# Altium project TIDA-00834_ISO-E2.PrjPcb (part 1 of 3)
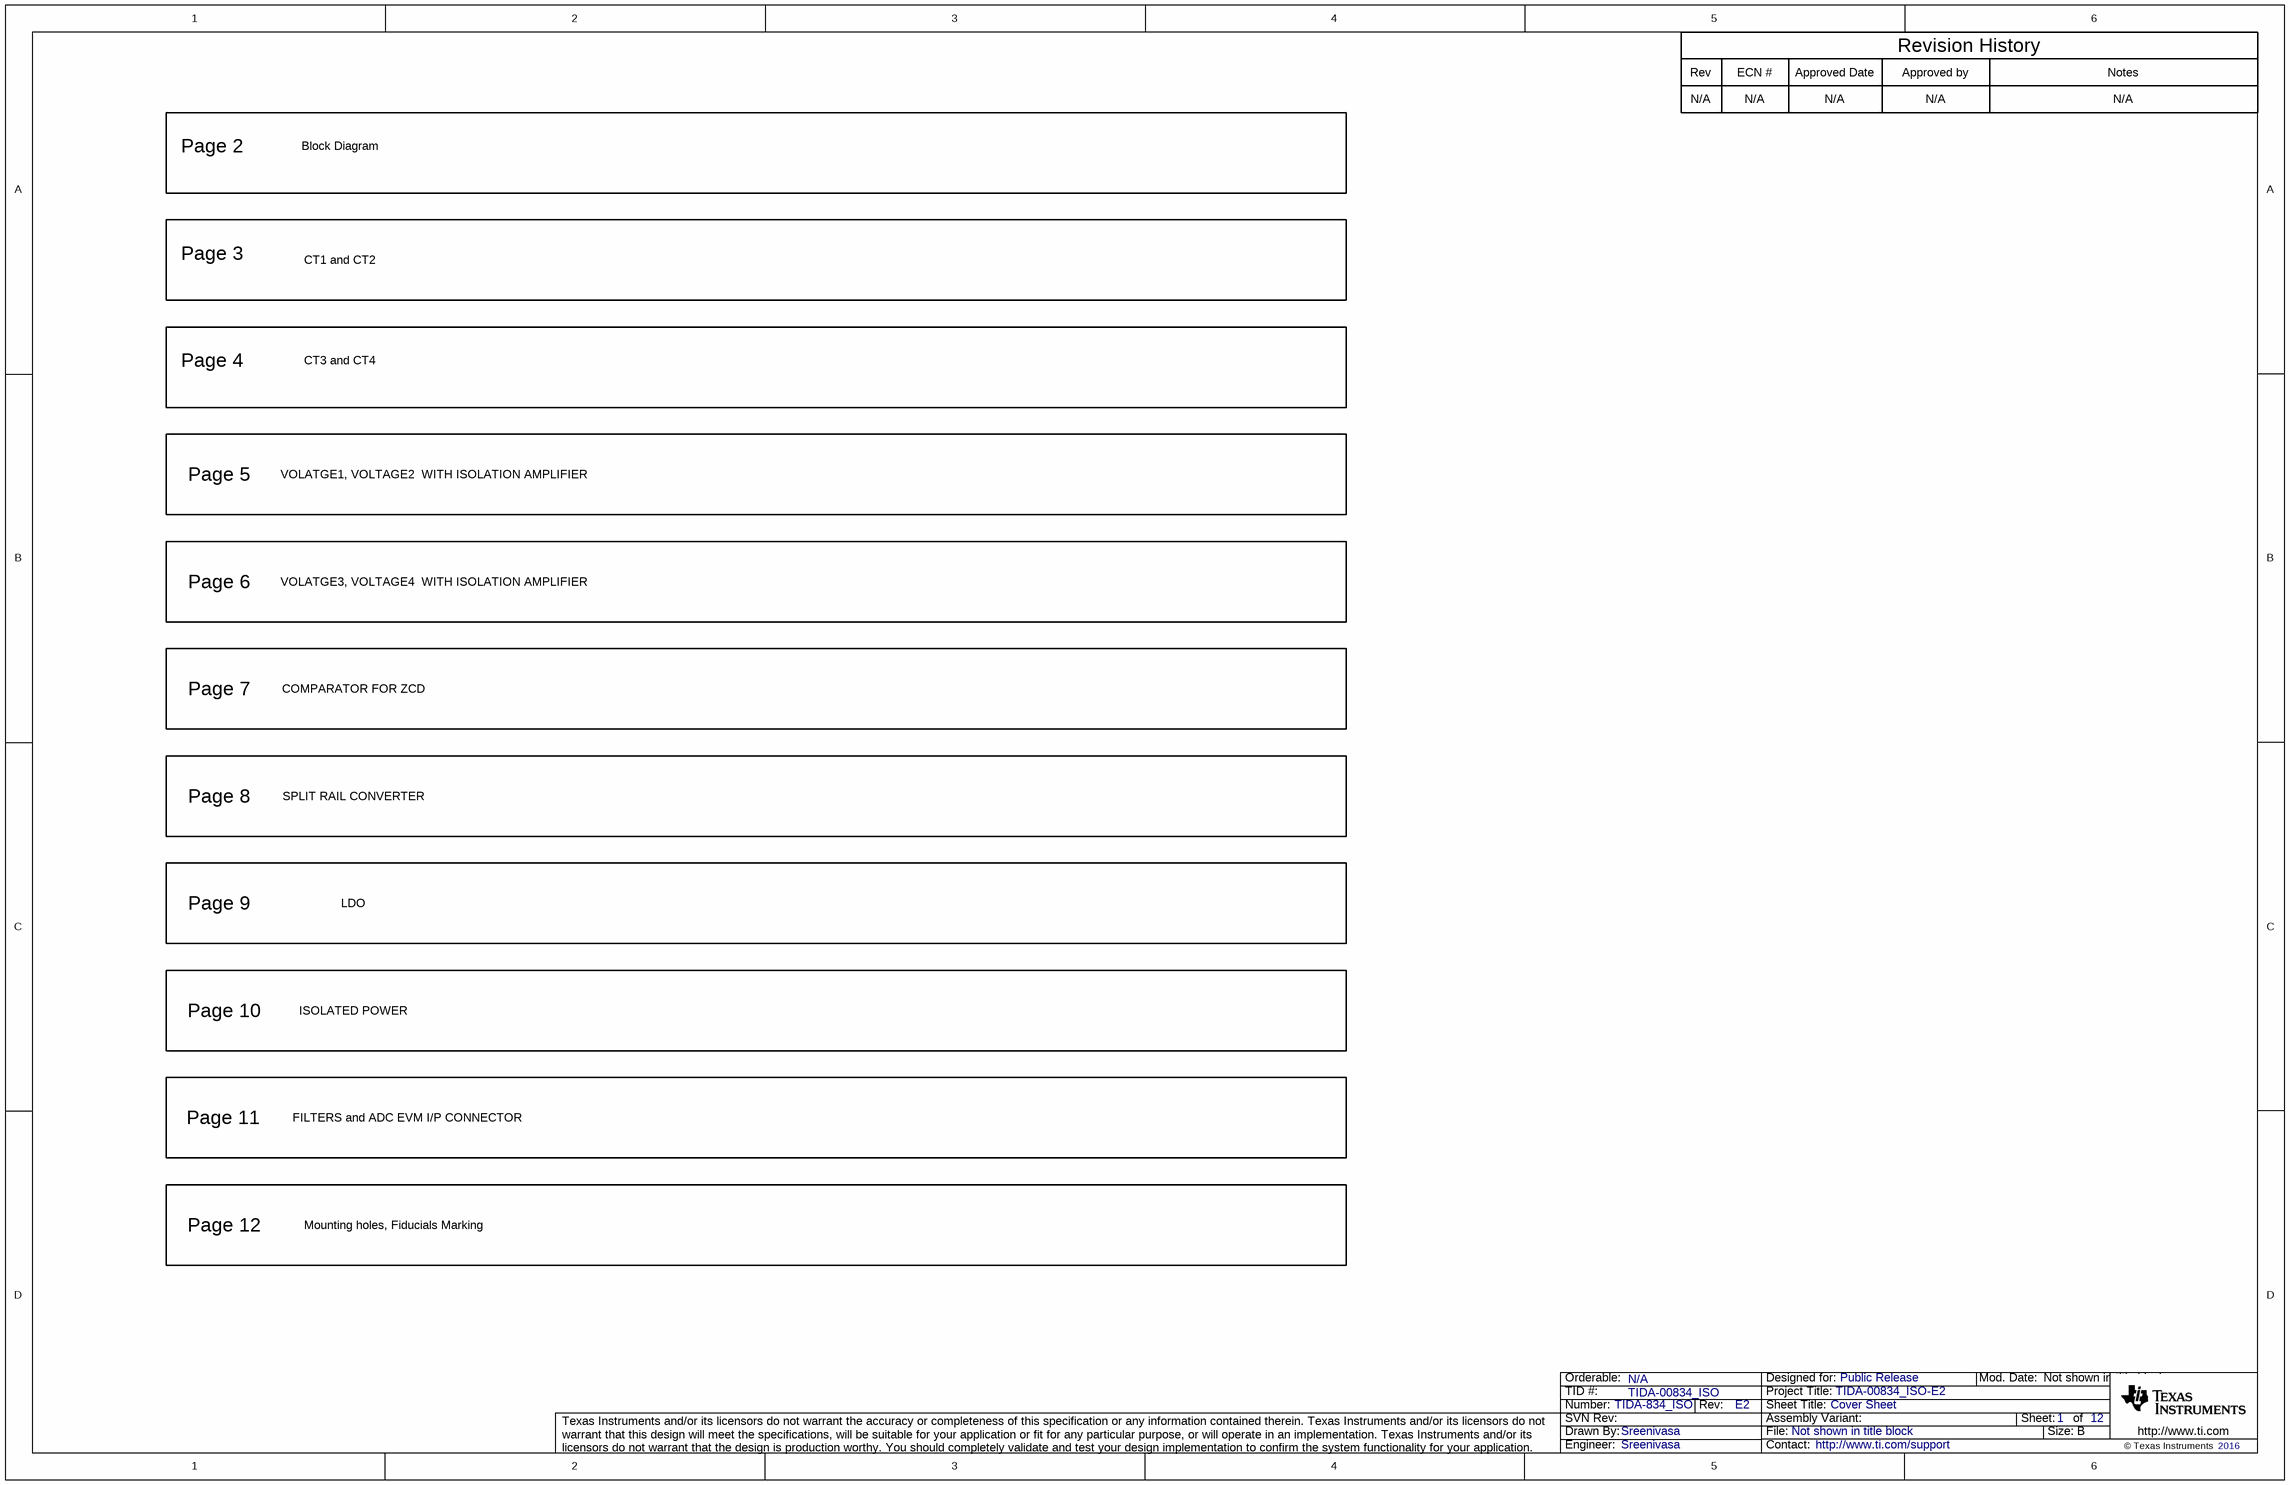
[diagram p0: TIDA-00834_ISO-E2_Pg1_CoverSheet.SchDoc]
CopyrightYear: 2016; EVM_Orderable: N/A; PCB_Layout: Manjunath M; PCB_Rev: E2; PRJ_Customer: Public Release; PRJ_Engineer: Sreenivasa; PRJ_Number: TIDA-834_ISO; PRJ_Title: TIDA-00834_ISO-E2; SCH_Rev: E2; TechSupport: http://www.ti.com/support; TID: TIDA-00834_ISO
12 sheets, 678 parts. Net scope: flat (ports and power ports of the same name join across sheets).
Board file: TIDA-00834_ISO-E2_PCB.PcbDoc
Sheets:
  TIDA-00834_ISO-E2_Pg1_CoverSheet.SchDoc
  TIDA-00834_ISO-E2_Pg2_Block Diagram.SchDoc
  TIDA-00834_ISO-E2_Pg3_CT1_CT2.SchDoc
  TIDA-00834_ISO-E2_Pg4_CT3_CT4.SchDoc
  TIDA-00834_ISO-E2_Pg5_VOLTAGE.SchDoc
  TIDA-00834_ISO-E2_Pg6_VOLTAGE2.SchDoc
  TIDA-00834_ISO-E2_Pg7_ COMPARATOR.SchDoc
  TIDA-00834_ISO-E2_Pg8_Split Rail Converter.SchDoc
  TIDA-00834_ISO-E2_Pg9_LDO.SchDoc
  TIDA-00834_ISO-E2_Pg10_ ISOPOWER.SchDoc
  TIDA-00834_ISO-E2_Pg11_Filters.SchDoc
  TIDA-00834_ISO-E2_Pg12_EVM_Hardware.SchDoc

## Sheet TIDA-00834_ISO-E2_Pg1_CoverSheet.SchDoc: Cover Sheet
size 431 x 279 mm; Date: Not shown in title block; ApprovedBy: Not shown in title block; CheckedBy: Not shown in title block; Author: Not shown in title block; CompanyName: Not shown in title block; DrawnBy: Sreenivasa; Engineer: Not shown in title block; Organization: Not shown in title block; Address1: Not shown in title block; Address2: Not shown in title block; Address3: Not shown in title block; Address4: Not shown in title block; DocumentNumber: 1; Revision: Use project parameter SCH_Rev; SheetNumber: 1; SheetTotal: 12; PageSetup: Record=PageOptions¦CenterHorizontal=True¦CenterVertical=True¦PrintScale=1.00¦XCorrection=1.00¦YCorrection=1.00¦PrintKind=0¦BorderSize=5000000¦LeftOffset=0¦BottomOffset=0¦Orientation=2¦PaperLength=1000¦PaperWidth=1000¦Scale=100¦PaperSource=15¦PrintQuality=600¦MediaType=1¦DitherType=10¦PaperKind=Letter¦PrintScaleMode=1

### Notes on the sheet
- Rev
- N/A
- ECN #
- Approved Date
- Approved by
- Revision History
- Notes
- Page 2
- Block Diagram
- Page 3
- CT1 and CT2
- Page 4
- CT3 and CT4
- Page 5
- VOLATGE1, VOLTAGE2  WITH ISOLATION AMPLIFIER
- Page 6
- VOLATGE3, VOLTAGE4  WITH ISOLATION AMPLIFIER
- Page 7
- COMPARATOR FOR ZCD
- Page 8
- SPLIT RAIL CONVERTER
- Page 9
- LDO
- Page 10
- ISOLATED POWER
- Page 11
- FILTERS and ADC EVM I/P CONNECTOR
- Page 12
- Mounting holes, Fiducials Marking

## Sheet TIDA-00834_ISO-E2_Pg2_Block Diagram.SchDoc: Block Diagram
size 431 x 279 mm; Date: Not shown in title block; ApprovedBy: Not shown in title block; CheckedBy: Not shown in title block; Author: Not shown in title block; CompanyName: Not shown in title block; DrawnBy: Sreenivasa; Engineer: Not shown in title block; Organization: Not shown in title block; Address1: Not shown in title block; Address2: Not shown in title block; Address3: Not shown in title block; Address4: Not shown in title block; DocumentNumber: 1; Revision: Use project parameter SCH_Rev; SheetNumber: 2; SheetTotal: 12; PageSetup: Record=PageOptions¦CenterHorizontal=True¦CenterVertical=True¦PrintScale=1.00¦XCorrection=1.00¦YCorrection=1.00¦PrintKind=0¦BorderSize=5000000¦LeftOffset=0¦BottomOffset=0¦Orientation=2¦PaperLength=1000¦PaperWidth=1000¦Scale=100¦PaperSource=15¦PrintQuality=600¦MediaType=1¦DitherType=10¦PaperKind=Letter¦PrintScaleMode=1
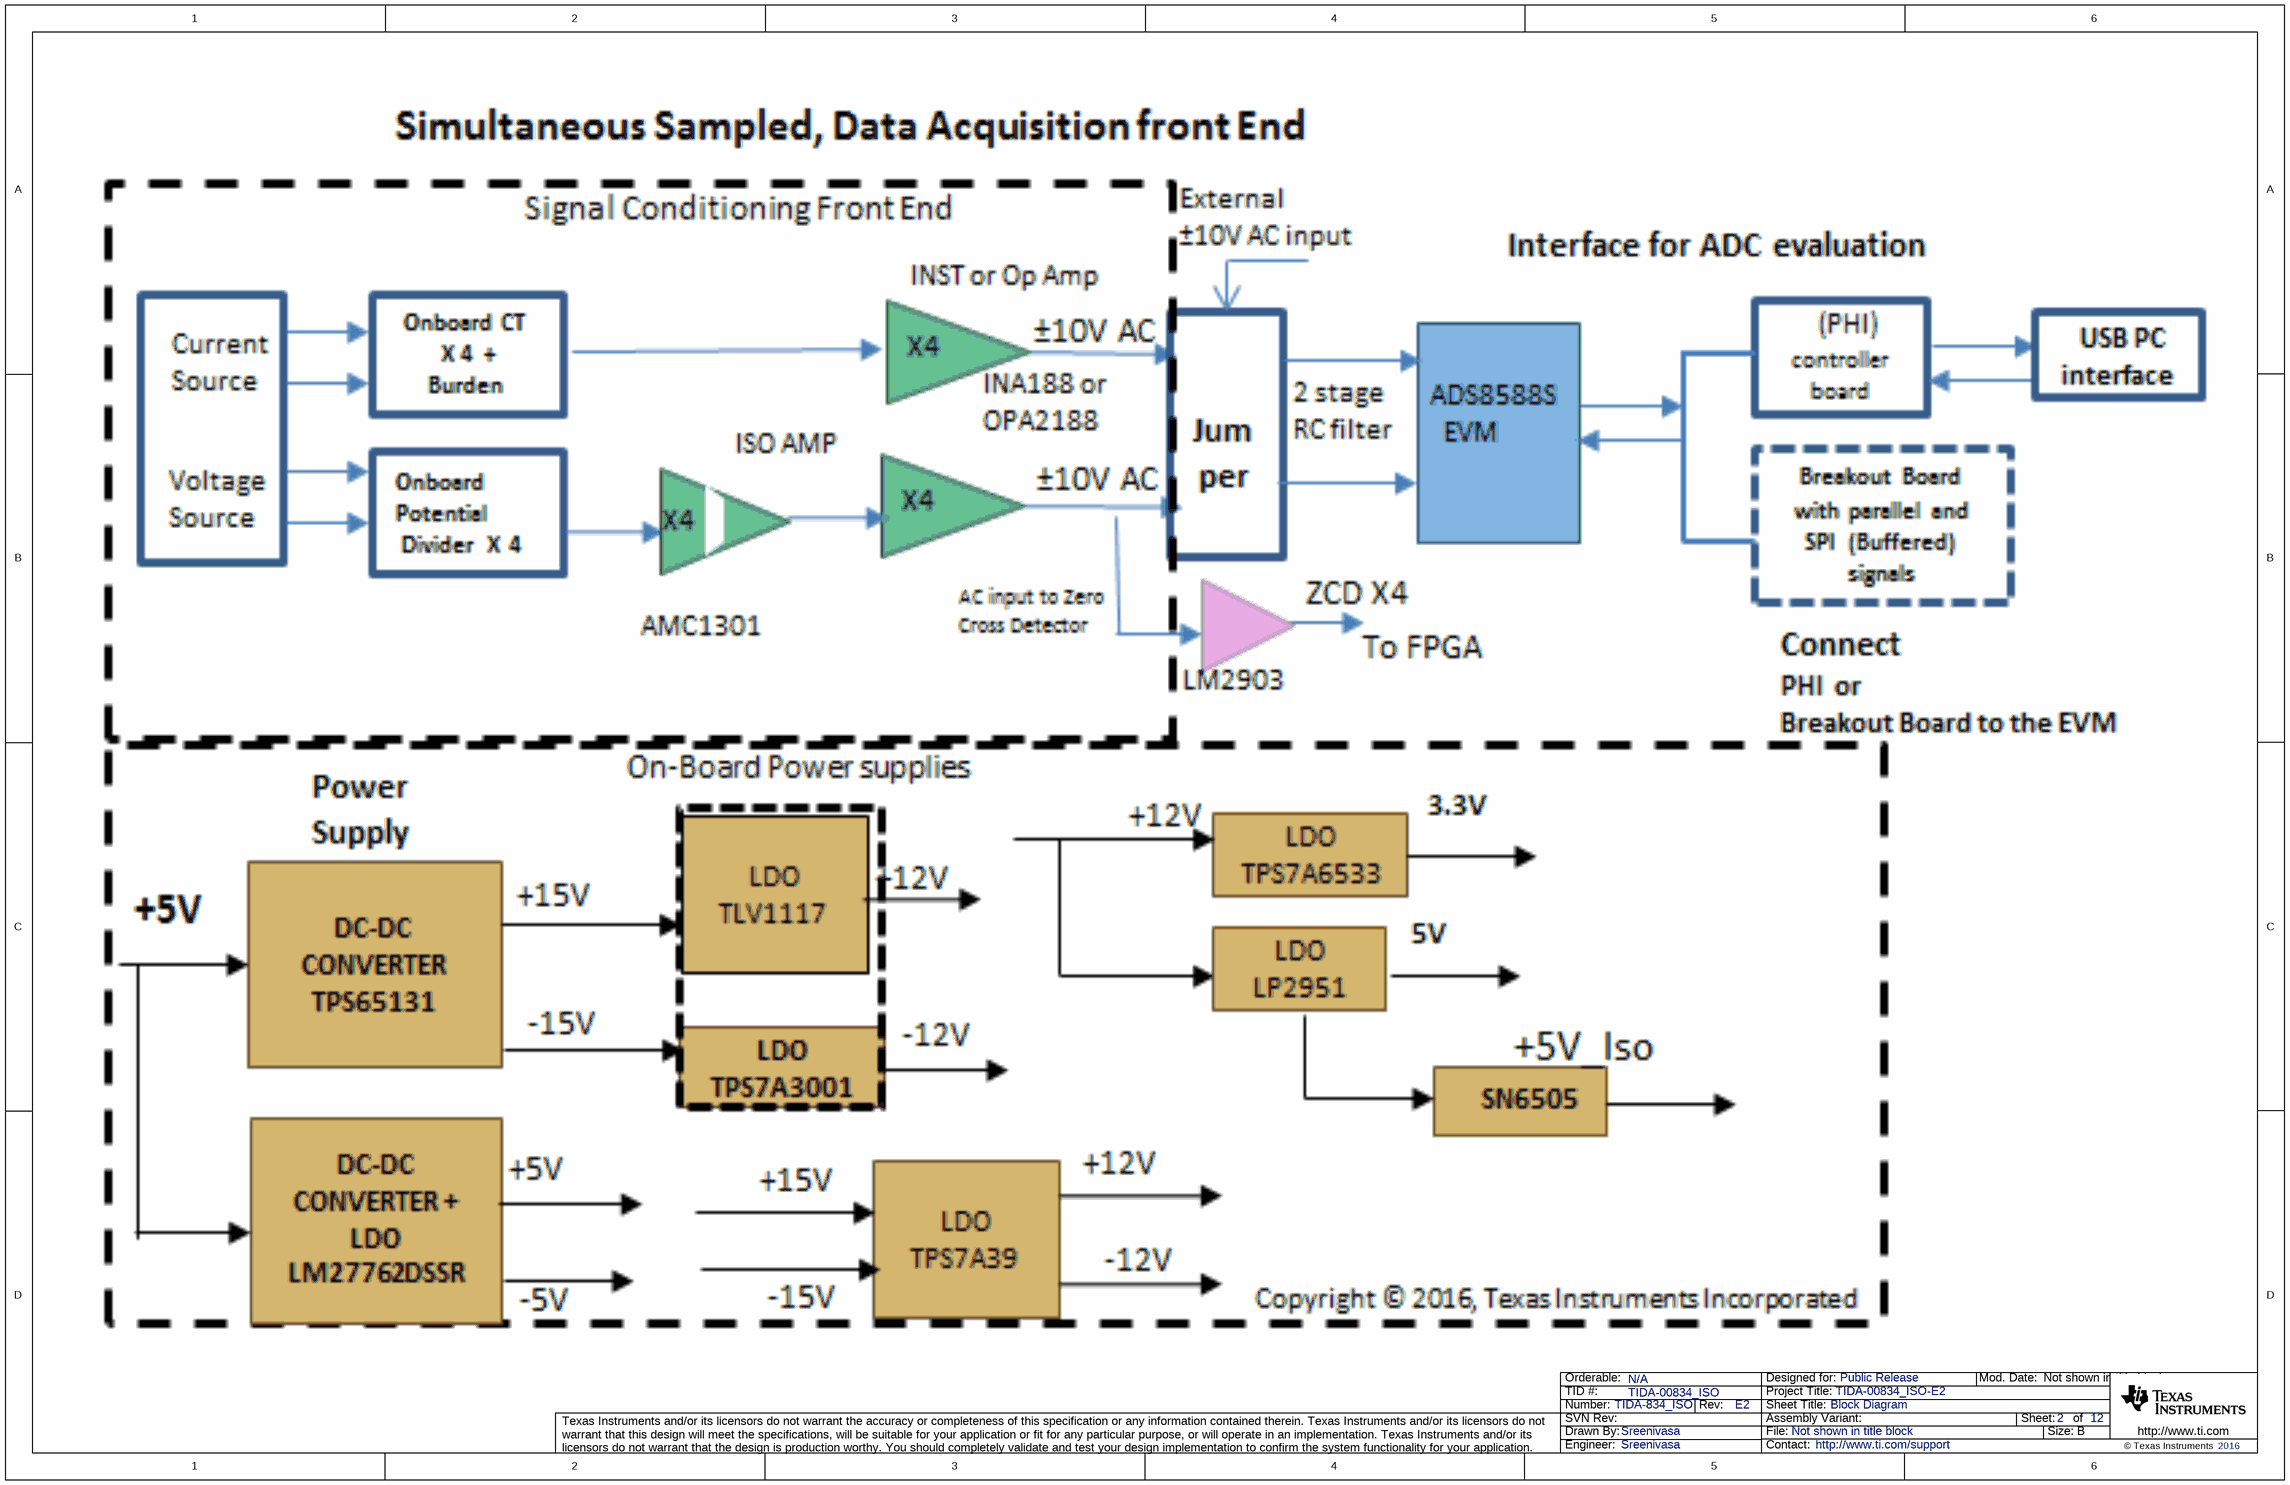
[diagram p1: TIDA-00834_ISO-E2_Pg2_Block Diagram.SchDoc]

## Sheet TIDA-00834_ISO-E2_Pg3_CT1_CT2.SchDoc: CT1 and CAT2
size 431 x 279 mm; Date: Not shown in title block; ApprovedBy: Not shown in title block; CheckedBy: Not shown in title block; Author: Not shown in title block; CompanyName: Not shown in title block; DrawnBy: Sreenivasa; Engineer: Not shown in title block; Organization: Not shown in title block; Address1: Not shown in title block; Address2: Not shown in title block; Address3: Not shown in title block; Address4: Not shown in title block; DocumentNumber: 1; Revision: Use project parameter SCH_Rev; SheetNumber: 3; SheetTotal: 12; PageSetup: Record=PageOptions¦CenterHorizontal=True¦CenterVertical=True¦PrintScale=1.00¦XCorrection=1.00¦YCorrection=1.00¦PrintKind=0¦BorderSize=5000000¦LeftOffset=0¦BottomOffset=0¦Orientation=2¦PaperLength=1000¦PaperWidth=1000¦Scale=100¦PaperSource=15¦PrintQuality=600¦MediaType=1¦DitherType=10¦PaperKind=Letter¦PrintScaleMode=1
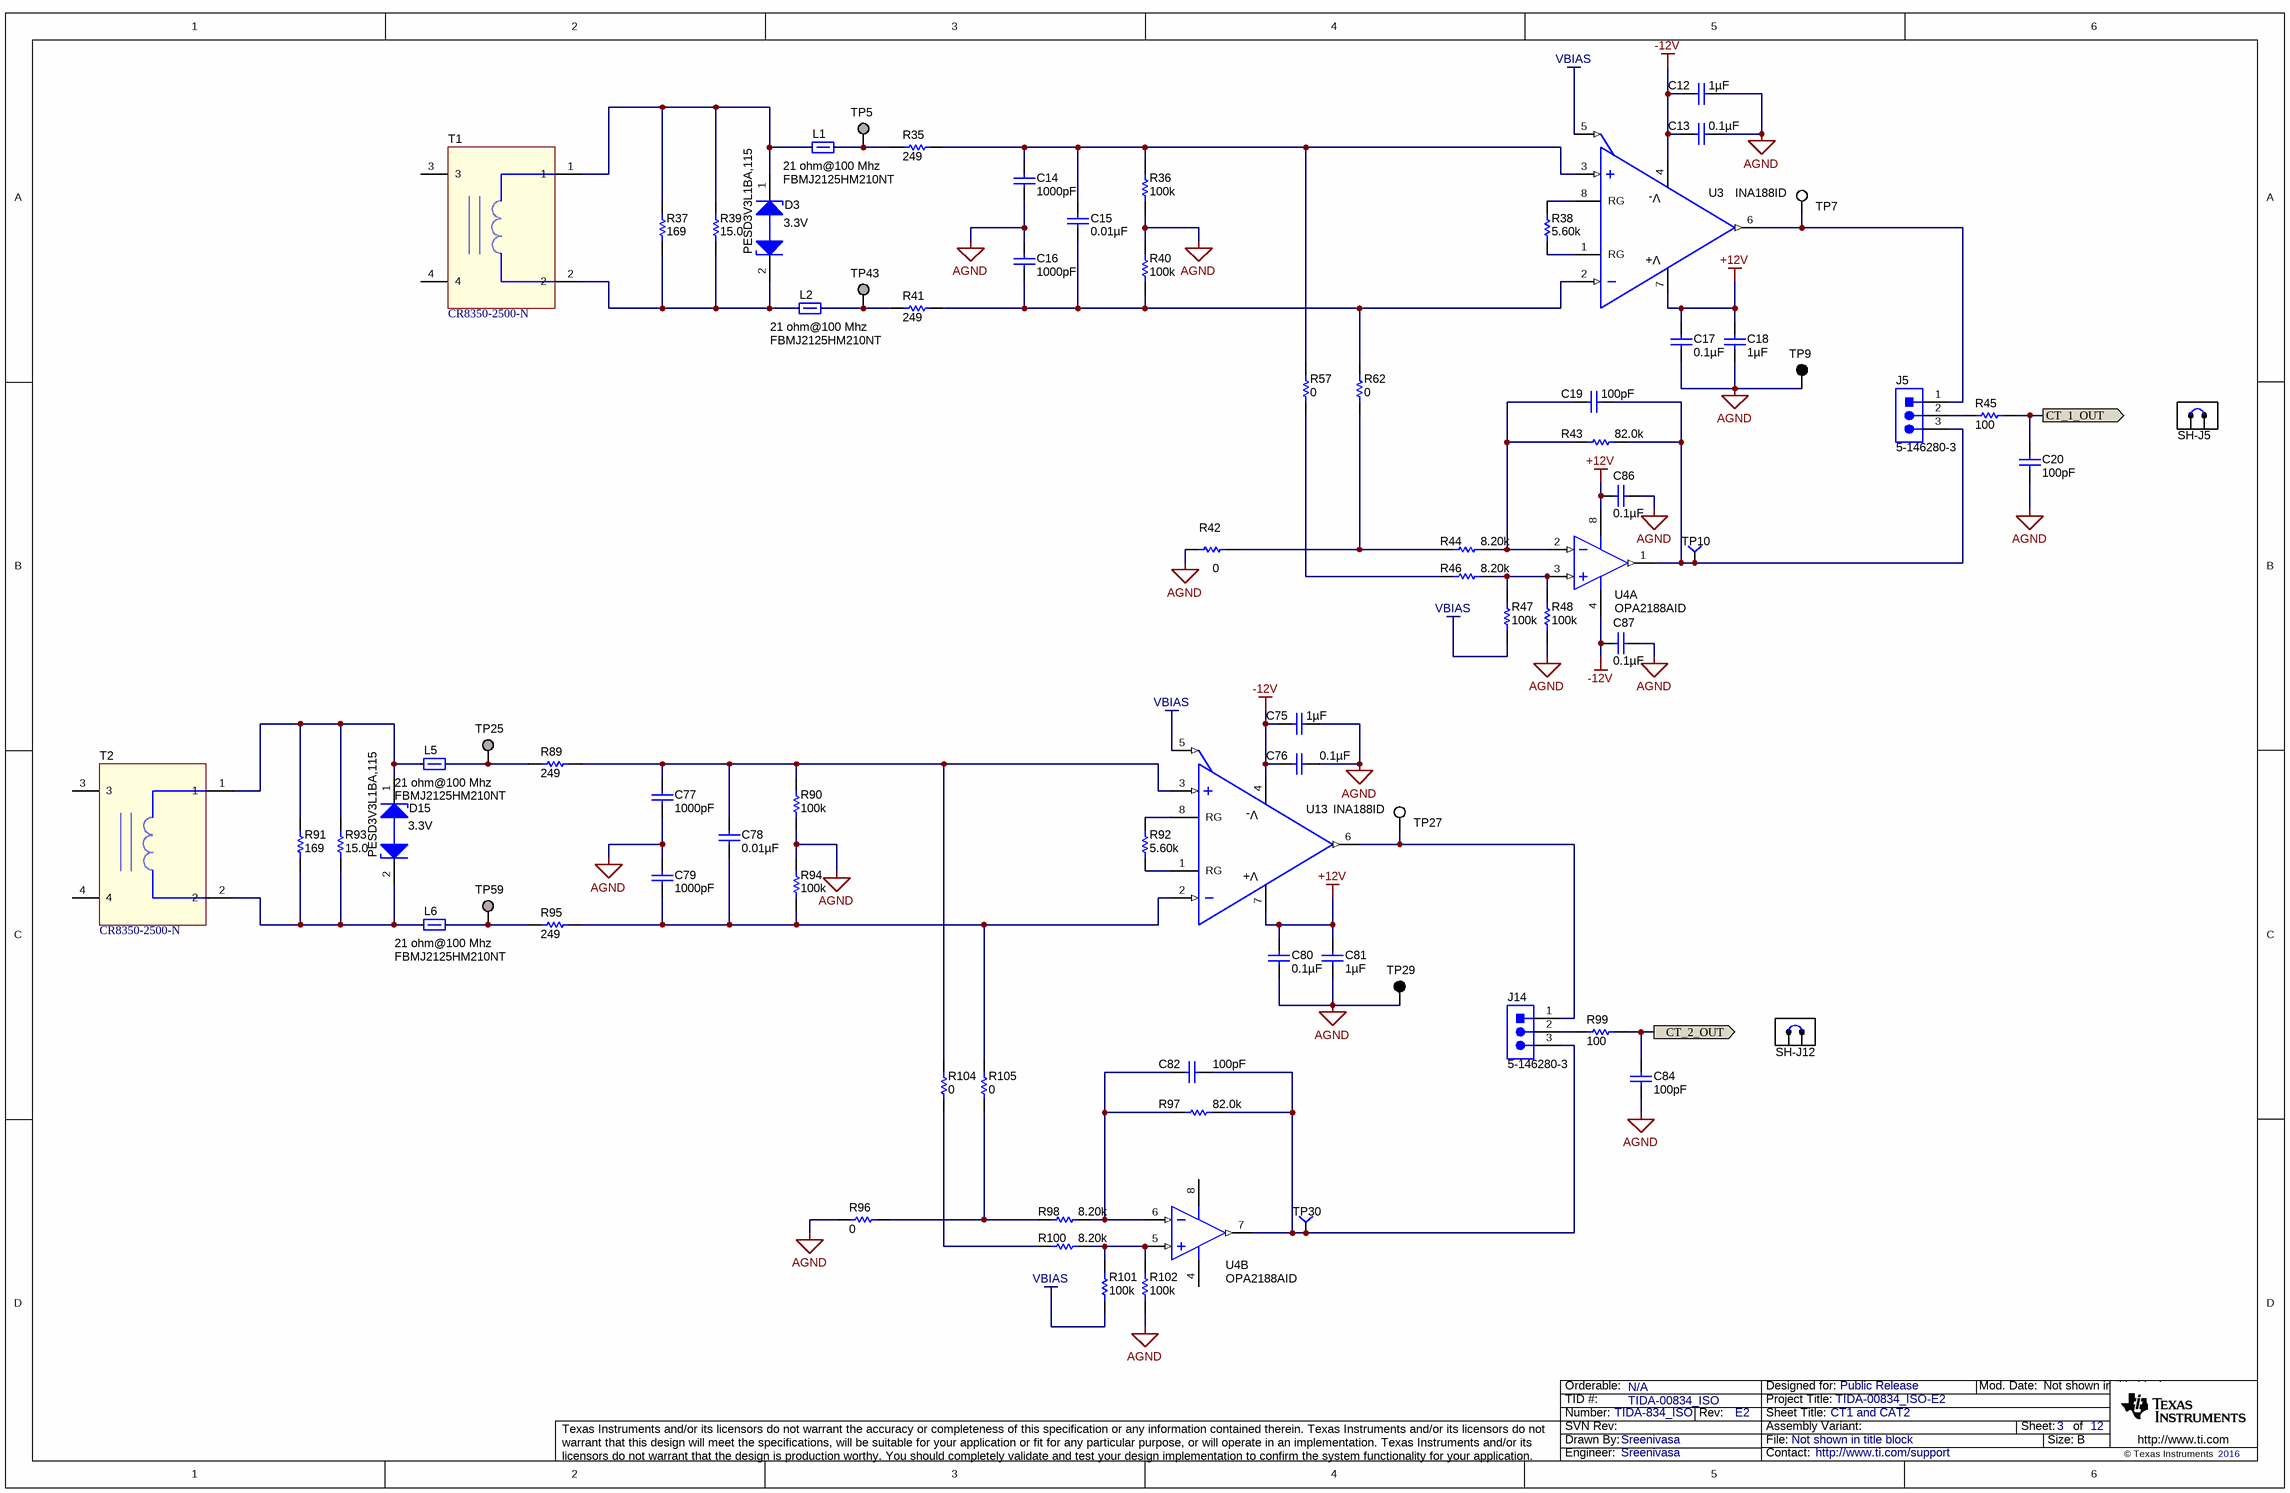
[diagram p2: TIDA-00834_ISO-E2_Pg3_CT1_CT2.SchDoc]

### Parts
C12  ValueDisplayed: 1µF  [0603]  (hidden comment: GRM188R61C105KA93D)
C13  ValueDisplayed: 0.1µF  [0603]  (hidden comment: CGA3E2X8R1E104K080AA)
C14  ValueDisplayed: 1000pF  [0603]  (hidden comment: C0603X102K5RACTU)
C15  ValueDisplayed: 0.01µF  [0603]  (hidden comment: 06031C103KAT2A)
C16  ValueDisplayed: 1000pF  [0603]  (hidden comment: C0603X102K5RACTU)
C17  ValueDisplayed: 0.1µF  [0603]  (hidden comment: CGA3E2X8R1E104K080AA)
C18  ValueDisplayed: 1µF  [0603]  (hidden comment: GRM188R61C105KA93D)
C19  ValueDisplayed: 100pF  [0603]  (hidden comment: 06033C101KAT2A)
C20  ValueDisplayed: 100pF  [0603]  (hidden comment: 06033C101KAT2A)
C75  ValueDisplayed: 1µF  [0603]  (hidden comment: GRM188R61C105KA93D)
C76  ValueDisplayed: 0.1µF  [0603]  (hidden comment: CGA3E2X8R1E104K080AA)
C77  ValueDisplayed: 1000pF  [0603]  (hidden comment: C0603X102K5RACTU)
C78  ValueDisplayed: 0.01µF  [0603]  (hidden comment: 06031C103KAT2A)
C79  ValueDisplayed: 1000pF  [0603]  (hidden comment: C0603X102K5RACTU)
C80  ValueDisplayed: 0.1µF  [0603]  (hidden comment: CGA3E2X8R1E104K080AA)
C81  ValueDisplayed: 1µF  [0603]  (hidden comment: GRM188R61C105KA93D)
C82  ValueDisplayed: 100pF  [0603]  (hidden comment: 06033C101KAT2A)
C84  ValueDisplayed: 100pF  [0603]  (hidden comment: 06033C101KAT2A)
C86  ValueDisplayed: 0.1µF  [0603]  (hidden comment: CGA3E2X8R1E104K080AA)
C87  ValueDisplayed: 0.1µF  [0603]  (hidden comment: CGA3E2X8R1E104K080AA)
D3  PESD3V3L1BA,115  value 3.3V  [DIO_SOD323]
D15  PESD3V3L1BA,115  value 3.3V  [DIO_SOD323]
J5  5-146280-3  [TE_5-146280-3]
J14  5-146280-3  [TE_5-146280-3]
L1  value 21 ohm@100 Mhz  [0805_HV]  (hidden comment: FBMJ2125HM210NT)
L2  value 21 ohm@100 Mhz  [0805_HV]  (hidden comment: FBMJ2125HM210NT)
L5  value 21 ohm@100 Mhz  [0805_HV]  (hidden comment: FBMJ2125HM210NT)
L6  value 21 ohm@100 Mhz  [0805_HV]  (hidden comment: FBMJ2125HM210NT)
R35  ValueDisplayed: 249  [0603]  (hidden comment: RT0603BRD07249RL)
R36  ValueDisplayed: 100k  [0603]  (hidden comment: RC0603FR-07100KL)
R37  ValueDisplayed: 169  [0603]  (hidden comment: RC0603FR-07169RL)
R38  ValueDisplayed: 5.60k  [0603]  (hidden comment: RG1608P-562-B-T5)
R39  ValueDisplayed: 15.0  [0603]  (hidden comment: CRCW060315R0FKEA)
R40  ValueDisplayed: 100k  [0603]  (hidden comment: RC0603FR-07100KL)
R41  ValueDisplayed: 249  [0603]  (hidden comment: RT0603BRD07249RL)
R42  ValueDisplayed: 0  [0603]  (hidden comment: RC0603JR-070RL)
R43  ValueDisplayed: 82.0k  [0603]  (hidden comment: RG1608P-823-B-T5)
R44  ValueDisplayed: 8.20k  [0603]  (hidden comment: RC0603FR-078K2L)
R45  value 100  [0603]  (hidden comment: CRCW0603100RFKEA)
R46  ValueDisplayed: 8.20k  [0603]  (hidden comment: RC0603FR-078K2L)
R47  ValueDisplayed: 100k  [0603]  (hidden comment: RC0603FR-07100KL)
R48  ValueDisplayed: 100k  [0603]  (hidden comment: RC0603FR-07100KL)
R57  ValueDisplayed: 0  [0603]  (hidden comment: RC0603JR-070RL)
R62  ValueDisplayed: 0  [0603]  (hidden comment: RC0603JR-070RL)
R89  ValueDisplayed: 249  [0603]  (hidden comment: RT0603BRD07249RL)
R90  ValueDisplayed: 100k  [0603]  (hidden comment: RC0603FR-07100KL)
R91  ValueDisplayed: 169  [0603]  (hidden comment: RC0603FR-07169RL)
R92  ValueDisplayed: 5.60k  [0603]  (hidden comment: RG1608P-562-B-T5)
R93  ValueDisplayed: 15.0  [0603]  (hidden comment: CRCW060315R0FKEA)
R94  ValueDisplayed: 100k  [0603]  (hidden comment: RC0603FR-07100KL)
R95  ValueDisplayed: 249  [0603]  (hidden comment: RT0603BRD07249RL)
R96  ValueDisplayed: 0  [0603]  (hidden comment: RC0603JR-070RL)
R97  ValueDisplayed: 82.0k  [0603]  (hidden comment: RG1608P-823-B-T5)
R98  ValueDisplayed: 8.20k  [0603]  (hidden comment: RC0603FR-078K2L)
R99  value 100  [0603]  (hidden comment: CRCW0603100RFKEA)
R100  ValueDisplayed: 8.20k  [0603]  (hidden comment: RC0603FR-078K2L)
R101  ValueDisplayed: 100k  [0603]  (hidden comment: RC0603FR-07100KL)
R102  ValueDisplayed: 100k  [0603]  (hidden comment: RC0603FR-07100KL)
R104  ValueDisplayed: 0  [0603]  (hidden comment: RC0603JR-070RL)
R105  ValueDisplayed: 0  [0603]  (hidden comment: RC0603JR-070RL)
SH-J5  881545-2  [TE_881545-2]  (value not drawn)  (mechanical)
SH-J12  881545-2  [TE_881545-2]  (value not drawn)  (mechanical)
T1  CR8350-2500-N  [XFMR_CR8350-2500-N]
T2  CR8350-2500-N  [XFMR_CR8350-2500-N]
TP5  Suggest using a net name here  [Keystone1573-2]  (value not drawn)
TP7  5002  [Keystone5002]  (value not drawn)
TP9  5001  [Keystone5001]  (value not drawn)
TP10  TP-040_RND  [TP_H045P075]  (value not drawn)
TP25  Suggest using a net name here  [Keystone1573-2]  (value not drawn)
TP27  5002  [Keystone5002]  (value not drawn)
TP29  5001  [Keystone5001]  (value not drawn)
TP30  TP-040_RND  [TP_H045P075]  (value not drawn)
TP43  Suggest using a net name here  [Keystone1573-2]  (value not drawn)
TP59  Suggest using a net name here  [Keystone1573-2]  (value not drawn)
U3  INA188ID  [D0008A_N]
U4  OPA2188AID  [D0008A_N]  (parts A,B of 2)
U13  INA188ID  [D0008A_N]

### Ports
CT_1_OUT (out), CT_2_OUT (out)

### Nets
+12V: C17.1 C18.1 C80.1 C81.1 C86.1 U3.7(V+) U4.8(V+) U13.7(V+)
-12V: C12.1 C13.1 C75.1 C76.1 C87.1 U3.4(V-) U4.4(V-) U13.4(V-)
AGND: C12.2 C13.2 C14.2 C16.1 C17.2 C18.2 C20.2 C75.2 C76.2 C77.2 C79.1 C80.2 C81.2 C84.2 C86.2 C87.2 R36.1 R40.2 R42.1 R48.1 R90.1 R94.2 R96.2 R102.1 TP9.1 TP29.1
VBIAS: R47.1 R101.1 U3.5(REF) U13.5(REF)
CT_1_OUT: C20.1 R45.2 ; port CT_1_OUT
CT_2_OUT: C84.1 R99.2 ; port CT_2_OUT
NetC14_1: C14.1 C15.1 R35.2 R36.2 R57.2 U3.3(IN+)
NetC15_2: C15.2 C16.2 R40.1 R41.2 R62.2 U3.2(IN-)
NetC19_1: C19.1 R43.2 R44.1 U4.2(IN_A-)
NetC19_2: C19.2 J5.3 R43.1 TP10.1 U4.1(OUT_A)
NetC77_1: C77.1 C78.1 R89.2 R90.2 R104.2 U13.3(IN+)
NetC78_2: C78.2 C79.2 R94.1 R95.2 R105.2 U13.2(IN-)
NetC82_1: C82.1 R97.2 R98.1 U4.6(IN_B-)
NetC82_2: C82.2 J14.3 R97.1 TP30.1 U4.7(OUT_B)
NetD3_1: D3.1(K) L1.1 R37.2 R39.2 T1.1
NetD3_2: D3.2(K) L2.1 R37.1 R39.1 T1.2
NetD15_1: D15.1(K) L5.1 R91.2 R93.2 T2.1
NetD15_2: D15.2(K) L6.1 R91.1 R93.1 T2.2
NetJ5_1: J5.1 TP7.1 U3.6(OUT)
NetJ5_2: J5.2 R45.1
NetJ14_1: J14.1 TP27.1 U13.6(OUT)
NetJ14_2: J14.2 R99.1
NetL1_2: L1.2 R35.1 TP5.1
NetL2_2: L2.2 R41.1 TP43.1
NetL5_2: L5.2 R89.1 TP25.1
NetL6_2: L6.2 R95.1 TP59.1
NetR38_1: R38.1 U3.1(RG)
NetR38_2: R38.2 U3.8(RG)
NetR42_2: R42.2 R44.2 R62.1
NetR46_1: R46.1 R47.2 R48.2 U4.3(IN_A+)
NetR46_2: R46.2 R57.1
NetR92_1: R92.1 U13.1(RG)
NetR92_2: R92.2 U13.8(RG)
NetR96_1: R96.1 R98.2 R105.1
NetR100_1: R100.1 R101.2 R102.2 U4.5(IN_B+)
NetR100_2: R100.2 R104.1

Not connected (* = marked no-connect by the designer): T1 3 4; T2 3 4

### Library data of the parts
C12 C18 C75 C81 = C1608X5R1C105K: CAP, CERM, 1 µF, 16 V, +/- 10%, X5R, 0603; Manufacturer: Murata; Polarized: N; CompType: Capacitor; Value: 1uF; U/M: EA; Cap_F: 0.000001; Tolerance_%: 10; ESR_ohm: 0.0057; Value1: 0.0057 ohm; VDC_V: 16; Value2: 16V; TaMin_C: -55; TaMax_C: 85; AEC Category: Q200
C13 C17 C76 C80 C86 C87 = CGA3E2X8R1E104K080AA: CAP, CERM, 0.1 µF, 25 V, +/- 10%, X8R, AEC-Q200 Grade 0, 0603; Manufacturer: TDK; Polarized: N; CompType: Capacitor; Value: 0.1uF; U/M: EA; Cap_F: 0.0000001; Tolerance_%: 10; Value1: Unknown; VDC_V: 25; Value2: 25V; TaMin_C: -55; TaMax_C: 150; AEC Category: Q200; AEC Qualified: Y; AEC Grade: 0
C14 C16 C77 C79 = C0603X102K5RACTU: CAP, CERM, 1000 pF, 50 V, +/- 10%, X7R, 0603; Manufacturer: Kemet; Polarized: N; CompType: Capacitor; Value: 1000pF; U/M: EA; Cap_F: 0.000000001; Tolerance_%: 10; Value1: Unknown; VDC_V: 50; Value2: 50V; TaMin_C: -55; TaMax_C: 125; AEC Category: Q200
C15 C78 = 06031C103JAT2A: 10000pF 100V Ceramic Capacitor X7R 0603; Manufacturer: AVX; Polarized: N; Value: 0.01uF; U/M: EA; Cap_F: 0.00000001; Tolerance_%: 5; ESR_ohm: 0.098; Value1: 0.098 ohm; VDC_V: 100; TaMin_C: -55; TaMax_C: 125; AEC Category: Q200
C19 C20 C82 C84 = 06033C101KAT2A: CAP, CERM, 100pF, 25V, +/-10%, X7R, 0603; Manufacturer: AVX; Polarized: N; CompType: Capacitor; U/M: EA; Cap_F: 0.0000000001; Tolerance_%: 10; Value1: Unknown; VDC_V: 25; TaMin_C: -55; TaMax_C: 125
D3 D15 = PESD3V3L1BA: DIODE, TVS, BIDIRECTIONAL, 3.3VWM, 26VC, SOD323; Manufacturer: NXP Semiconductor; SymbolCreator: x0199378
J5 J14 = 5-146280-3: Header, 2.54mm, 3x1, Gold, TH; Manufacturer: TE Connectivity; SymbolCreator: a0799628; Pitch_mm: 2.54; Gender: Male; Shrouded: N; Row_Count: 1
L1 L2 L5 L6 = FBMJ2125HM210NT: Ferrite Bead, 21 ohm @ 100 MHz, 6 A, 0805; Manufacturer: Taiyo Yuden; Imax_A: 6; DCR_ohm: 0.004; Value1: 0.004 ohm; Value2: 6A; ZTyp@100MHz_Ohm: 21
R35 R41 R89 R95 = RT0603BRD07249RL: RES, 249, 0.1%, 0.1 W, 0603; Manufacturer: Yageo America; CompType: Resistor; Value: 249; Value_Code: 249R; Tolerance_%: 0.1; Value2: 0.1W; VDC_V: 75; TempCo: 25 ppm/C; EIA_Code: E192; U/M: EA; AEC Category: Q200
R36 R40 R47 R48 R90 R94 R101 R102 = RC0603FR-07100KL: RES, 100 k, 1%, 0.1 W, 0603; Manufacturer: Yageo America; CompType: Resistor; Value: 100k; Res_ohm: 100000; Tolerance_%: 1; Power_W: 0.1; Value2: 0.1W; VDC_V: 150; TempCo: 200 ppm/C; EIA_Code: E96; U/M: EA; AEC Category: Q200
R37 R91 = RC0603FR-07169RL: RES, 169, 1%, 0.1 W, 0603; Manufacturer: Yageo America; CompType: Resistor; Value: 169; Value_Code: 169R; Tolerance_%: 1; Power_W: 0.1; Value2: 0.1W; VDC_V: 150; TempCo: 200 ppm/C; SizeArea_mm2: 1.28; SizeX_mm: 1.6; SizeY_mm: 0.8; EIA_Code: E96; U/M: EA; AEC Category: Q200
R38 R92 = RG1608P-562-B-T5: RES, 5.60 k, 0.1%, 0.1 W, 0603; Manufacturer: Susumu Co Ltd; CompType: Resistor; Value: 5.60k; Res_ohm: 5600; Value_Code: 5k60; Tolerance_%: 0.1; Value2: 0.1W; VDC_V: 75; TempCo: 25 ppm/C; SizeArea_mm2: 1.28; SizeX_mm: 1.6; SizeY_mm: 0.8; SizeZ_mm: 1; U/M: EA; AEC Category: Q200
R39 R93 = CRCW060315R0FKEA: RES, 15.0, 1%, 0.1 W, 0603; Manufacturer: Vishay-Dale; CompType: Resistor; Value: 15.0; Res_ohm: 15; Value_Code: 15R0; Tolerance_%: 1; Power_W: 0.1; Value2: 0.1W; VDC_V: 75; TempCo: 100 ppm/C; SizeArea_mm2: 1.28; SizeX_mm: 1.6; SizeY_mm: 0.8; EIA_Code: E96; U/M: EA; AEC Category: Q200
R42 R57 R62 R96 R104 R105 = RC0603JR-070RL: RES, 0, 5%, 0.1 W, 0603; Manufacturer: Yageo America; CompType: Resistor; Value: 0; Value_Code: 0000; Tolerance_%: 5; Power_W: 0.1; Value2: 0.1W; VDC_V: 50; TempCo: 200 ppm/C; EIA_Code: E24; U/M: EA; AEC Category: Q200
R43 R97 = RG1608P-823-B-T5: RES, 82.0 k, 0.1%, 0.1 W, 0603; Manufacturer: Susumu Co Ltd; CompType: Resistor; Value: 82.0k; Res_ohm: 82000; Value_Code: 82k0; Tolerance_%: 0.1; Value2: 0.1W; VDC_V: 75; TempCo: 25 ppm/C; SizeArea_mm2: 1.28; SizeX_mm: 1.6; SizeY_mm: 0.8; SizeZ_mm: 1; U/M: EA; AEC Category: Q200
R44 R46 R98 R100 = RC0603FR-078K2L: RES, 8.20 k, 1%, 0.1 W, 0603; Manufacturer: Yageo America; CompType: Resistor; Value: 8.20k; Res_ohm: 8200; Value_Code: 8k20; Tolerance_%: 1; Power_W: 0.1; Value2: 0.1W; VDC_V: 150; TempCo: 200 ppm/C; U/M: EA; AEC Category: Q200
R45 R99 = CRCW0603100RFKEA: RES, 100 ohm, 1%, 0.1W, 0603; Manufacturer: Vishay-Dale; CompType: Resistor; Value_Code: 100R; Tolerance_%: 1; Power_W: 0.1; VDC_V: 75; TempCo: 100 ppm/C; EIA_Code: E96; U/M: EA
SH-J5 SH-J12 = 881545-2: Shunt, 100mil, Gold plated, Black; Manufacturer: TE Connectivity
T1 T2 = CR8350-2500-N: CURRENT TRANSFORMER, 20-1 KHz, 57 OHM, VERTICAL, THRU-4P; Manufacturer: CR MAGNETICS; SymbolCreator: x0199378
TP5 TP25 TP43 TP59 = 1573-2: Terminal, Turret, TH, Double; Manufacturer: Keystone; CompType: Turret Terminal; U/M: EA
TP7 TP27 = 5002: Test Point, Miniature, White, TH; Manufacturer: Keystone; CompType: Test Point Loop; U/M: EA
TP9 TP29 = 5001: Test Point, Miniature, Black, TH; Manufacturer: Keystone; CompType: Test Point Loop; U/M: EA
TP10 TP30 = TP-040_RND: Test Point, O.040 Hole; Manufacturer: STD; Value: STD
U3 U13 = INA188D: INA188 Precision, Zero-Drift, Rail-to-Rail Out, High Voltage Instrumentation Amplifier, D0008A; Manufacturer: Texas Instruments; SymbolCreator: Altium; CompType: IC; U/M: EA
U4 = OPA2188AID: 0.03 uV/degC, 6 uV Vos, Low Noise, Rail-to-Rail Output, Zero-Drift Operational Amplifier, 4 to 36 V, -40 to 105 degC, 8-pin SOIC (D0008A), Green (RoHS & no Sb/Br); Manufacturer: Texas Instruments; Alternate PartNumber: Equivalent; CMRR(Min)(dB): 120; GBW(Typ)(MHz): 2; IIB(Max)(pA): 850; Iq per channel(Max)(mA): 0.475; Offset Drift(Typ)(uV/C): 0.03; Packing: TUBE; Rating: Catalog; Slew Rate(Typ)(V/us): 0.8; Sub Family: High Supply Voltage Amplifier (>=30V), Low Noise Amp (<=10nV/rtHz), Low Offset Voltage Amplifier (<=500uV), Low Power Amp (<=500uA), Precision Amplifier, Zero Drift Precision Amplifier; Total Supply Voltage(Max)(+5V is 5, +/-5V is 10): 36; Total Supply Voltage(Min)(+5V is 5, +/-5V is 10): 4; Vio (25C)(Max)(mV): 0.025

## Sheet TIDA-00834_ISO-E2_Pg4_CT3_CT4.SchDoc: CT3 and CT4
size 431 x 279 mm; Date: Not shown in title block; ApprovedBy: Not shown in title block; CheckedBy: Not shown in title block; Author: Not shown in title block; CompanyName: Not shown in title block; DrawnBy: Sreenivasa; Engineer: Not shown in title block; Organization: Not shown in title block; Address1: Not shown in title block; Address2: Not shown in title block; Address3: Not shown in title block; Address4: Not shown in title block; DocumentNumber: 1; Revision: Use project parameter SCH_Rev; SheetNumber: 4; SheetTotal: 12; PageSetup: Record=PageOptions¦CenterHorizontal=True¦CenterVertical=True¦PrintScale=1.00¦XCorrection=1.00¦YCorrection=1.00¦PrintKind=0¦BorderSize=5000000¦LeftOffset=0¦BottomOffset=0¦Orientation=2¦PaperLength=1000¦PaperWidth=1000¦Scale=100¦PaperSource=15¦PrintQuality=600¦MediaType=1¦DitherType=10¦PaperKind=Letter¦PrintScaleMode=1
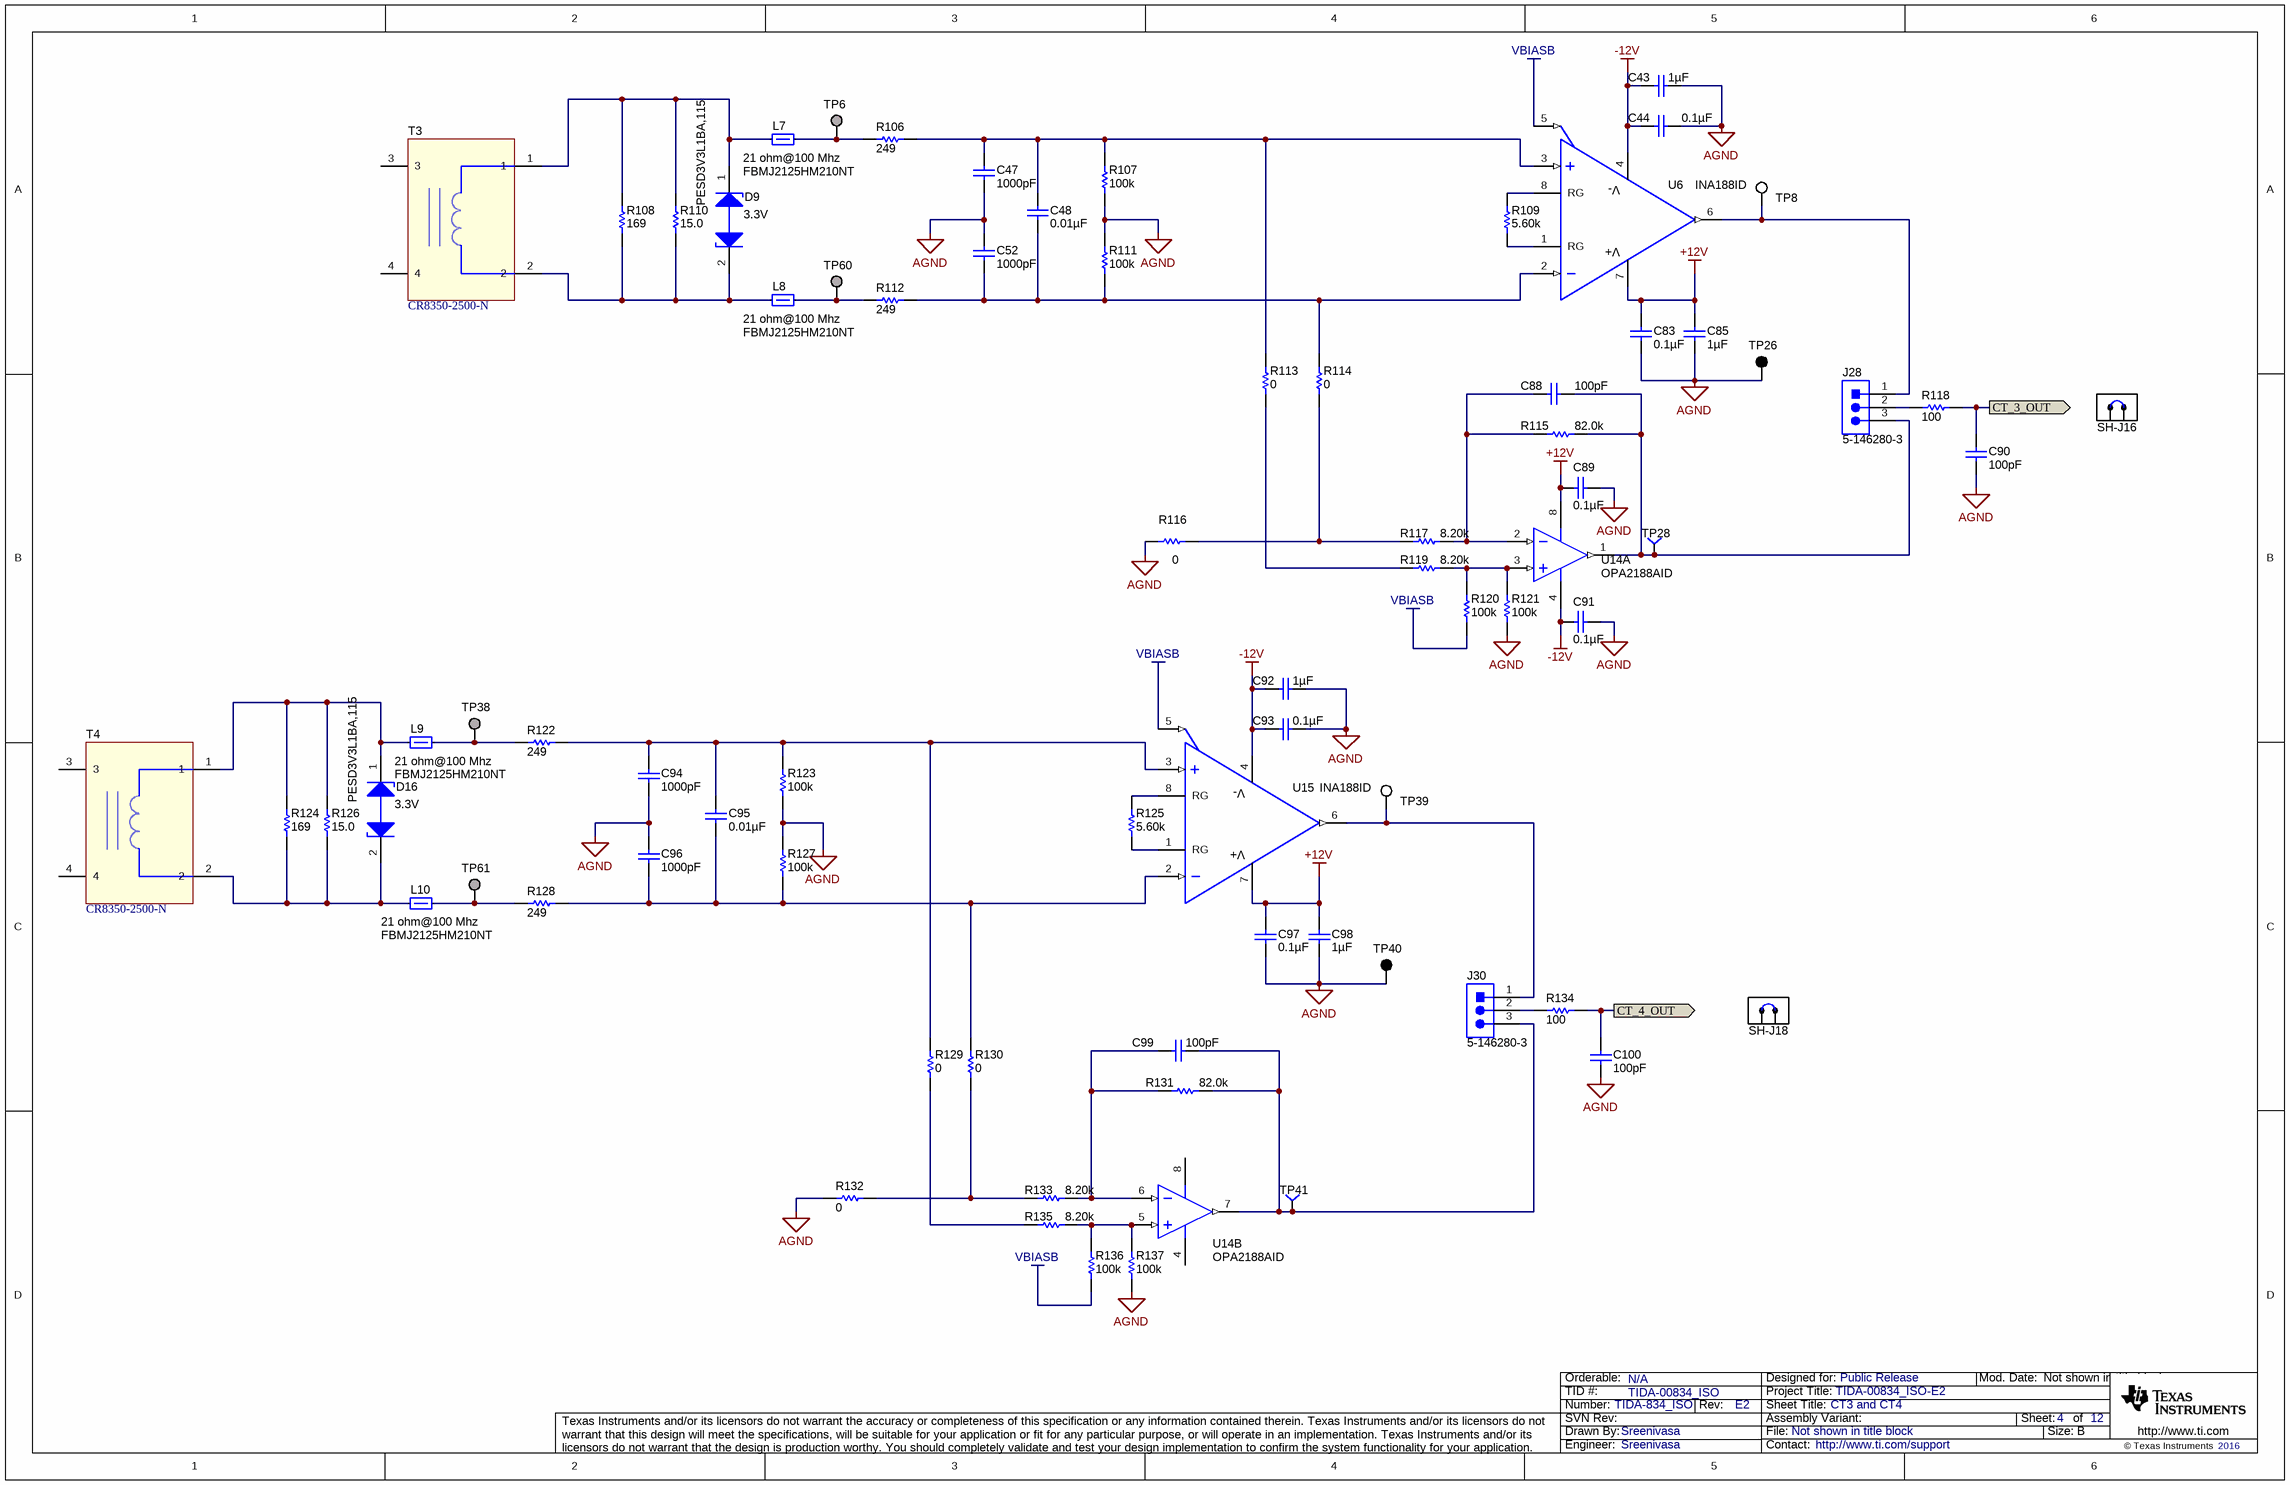
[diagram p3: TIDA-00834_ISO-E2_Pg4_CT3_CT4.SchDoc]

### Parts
C43  ValueDisplayed: 1µF  [0603]  (hidden comment: GRM188R61C105KA93D)
C44  ValueDisplayed: 0.1µF  [0603]  (hidden comment: CGA3E2X8R1E104K080AA)
C47  ValueDisplayed: 1000pF  [0603]  (hidden comment: C0603X102K5RACTU)
C48  ValueDisplayed: 0.01µF  [0603]  (hidden comment: 06031C103KAT2A)
C52  ValueDisplayed: 1000pF  [0603]  (hidden comment: C0603X102K5RACTU)
C83  ValueDisplayed: 0.1µF  [0603]  (hidden comment: CGA3E2X8R1E104K080AA)
C85  ValueDisplayed: 1µF  [0603]  (hidden comment: GRM188R61C105KA93D)
C88  ValueDisplayed: 100pF  [0603]  (hidden comment: 06033C101KAT2A)
C89  ValueDisplayed: 0.1µF  [0603]  (hidden comment: CGA3E2X8R1E104K080AA)
C90  ValueDisplayed: 100pF  [0603]  (hidden comment: 06033C101KAT2A)
C91  ValueDisplayed: 0.1µF  [0603]  (hidden comment: CGA3E2X8R1E104K080AA)
C92  ValueDisplayed: 1µF  [0603]  (hidden comment: GRM188R61C105KA93D)
C93  ValueDisplayed: 0.1µF  [0603]  (hidden comment: CGA3E2X8R1E104K080AA)
C94  ValueDisplayed: 1000pF  [0603]  (hidden comment: C0603X102K5RACTU)
C95  ValueDisplayed: 0.01µF  [0603]  (hidden comment: 06031C103KAT2A)
C96  ValueDisplayed: 1000pF  [0603]  (hidden comment: C0603X102K5RACTU)
C97  ValueDisplayed: 0.1µF  [0603]  (hidden comment: CGA3E2X8R1E104K080AA)
C98  ValueDisplayed: 1µF  [0603]  (hidden comment: GRM188R61C105KA93D)
C99  ValueDisplayed: 100pF  [0603]  (hidden comment: 06033C101KAT2A)
C100  ValueDisplayed: 100pF  [0603]  (hidden comment: 06033C101KAT2A)
D9  PESD3V3L1BA,115  value 3.3V  [DIO_SOD323]
D16  PESD3V3L1BA,115  value 3.3V  [DIO_SOD323]
J28  5-146280-3  [TE_5-146280-3]
J30  5-146280-3  [TE_5-146280-3]
L7  value 21 ohm@100 Mhz  [0805_HV]  (hidden comment: FBMJ2125HM210NT)
L8  value 21 ohm@100 Mhz  [0805_HV]  (hidden comment: FBMJ2125HM210NT)
L9  value 21 ohm@100 Mhz  [0805_HV]  (hidden comment: FBMJ2125HM210NT)
L10  value 21 ohm@100 Mhz  [0805_HV]  (hidden comment: FBMJ2125HM210NT)
R106  ValueDisplayed: 249  [0603]  (hidden comment: RT0603BRD07249RL)
R107  ValueDisplayed: 100k  [0603]  (hidden comment: RC0603FR-07100KL)
R108  ValueDisplayed: 169  [0603]  (hidden comment: RC0603FR-07169RL)
R109  ValueDisplayed: 5.60k  [0603]  (hidden comment: RG1608P-562-B-T5)
R110  ValueDisplayed: 15.0  [0603]  (hidden comment: CRCW060315R0FKEA)
R111  ValueDisplayed: 100k  [0603]  (hidden comment: RC0603FR-07100KL)
R112  ValueDisplayed: 249  [0603]  (hidden comment: RT0603BRD07249RL)
R113  ValueDisplayed: 0  [0603]  (hidden comment: RC0603JR-070RL)
R114  ValueDisplayed: 0  [0603]  (hidden comment: RC0603JR-070RL)
R115  ValueDisplayed: 82.0k  [0603]  (hidden comment: RG1608P-823-B-T5)
R116  ValueDisplayed: 0  [0603]  (hidden comment: RC0603JR-070RL)
R117  ValueDisplayed: 8.20k  [0603]  (hidden comment: RC0603FR-078K2L)
R118  value 100  [0603]  (hidden comment: CRCW0603100RFKEA)
R119  ValueDisplayed: 8.20k  [0603]  (hidden comment: RC0603FR-078K2L)
R120  ValueDisplayed: 100k  [0603]  (hidden comment: RC0603FR-07100KL)
R121  ValueDisplayed: 100k  [0603]  (hidden comment: RC0603FR-07100KL)
R122  ValueDisplayed: 249  [0603]  (hidden comment: RT0603BRD07249RL)
R123  ValueDisplayed: 100k  [0603]  (hidden comment: RC0603FR-07100KL)
R124  ValueDisplayed: 169  [0603]  (hidden comment: RC0603FR-07169RL)
R125  ValueDisplayed: 5.60k  [0603]  (hidden comment: RG1608P-562-B-T5)
R126  ValueDisplayed: 15.0  [0603]  (hidden comment: CRCW060315R0FKEA)
R127  ValueDisplayed: 100k  [0603]  (hidden comment: RC0603FR-07100KL)
R128  ValueDisplayed: 249  [0603]  (hidden comment: RT0603BRD07249RL)
R129  ValueDisplayed: 0  [0603]  (hidden comment: RC0603JR-070RL)
R130  ValueDisplayed: 0  [0603]  (hidden comment: RC0603JR-070RL)
R131  ValueDisplayed: 82.0k  [0603]  (hidden comment: RG1608P-823-B-T5)
R132  ValueDisplayed: 0  [0603]  (hidden comment: RC0603JR-070RL)
R133  ValueDisplayed: 8.20k  [0603]  (hidden comment: RC0603FR-078K2L)
R134  value 100  [0603]  (hidden comment: CRCW0603100RFKEA)
R135  ValueDisplayed: 8.20k  [0603]  (hidden comment: RC0603FR-078K2L)
R136  ValueDisplayed: 100k  [0603]  (hidden comment: RC0603FR-07100KL)
R137  ValueDisplayed: 100k  [0603]  (hidden comment: RC0603FR-07100KL)
SH-J16  881545-2  [TE_881545-2]  (value not drawn)  (mechanical)
SH-J18  881545-2  [TE_881545-2]  (value not drawn)  (mechanical)
T3  CR8350-2500-N  [XFMR_CR8350-2500-N]
T4  CR8350-2500-N  [XFMR_CR8350-2500-N]
TP6  Suggest using a net name here  [Keystone1573-2]  (value not drawn)
TP8  5002  [Keystone5002]  (value not drawn)
TP26  5001  [Keystone5001]  (value not drawn)
TP28  TP-040_RND  [TP_H045P075]  (value not drawn)
TP38  Suggest using a net name here  [Keystone1573-2]  (value not drawn)
TP39  5002  [Keystone5002]  (value not drawn)
TP40  5001  [Keystone5001]  (value not drawn)
TP41  TP-040_RND  [TP_H045P075]  (value not drawn)
TP60  Suggest using a net name here  [Keystone1573-2]  (value not drawn)
TP61  Suggest using a net name here  [Keystone1573-2]  (value not drawn)
U6  INA188ID  [D0008A_N]
U14  OPA2188AID  [D0008A_N]  (parts A,B of 2)
U15  INA188ID  [D0008A_N]

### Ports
CT_3_OUT (out), CT_4_OUT (out)

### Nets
+12V: C83.1 C85.1 C89.1 C97.1 C98.1 U6.7(V+) U14.8(V+) U15.7(V+)
-12V: C43.1 C44.1 C91.1 C92.1 C93.1 U6.4(V-) U14.4(V-) U15.4(V-)
AGND: C43.2 C44.2 C47.2 C52.1 C83.2 C85.2 C89.2 C90.2 C91.2 C92.2 C93.2 C94.2 C96.1 C97.2 C98.2 C100.2 R107.1 R111.2 R116.1 R121.1 R123.1 R127.2 R132.2 R137.1 TP26.1 TP40.1
VBIASB: R120.1 R136.1 U6.5(REF) U15.5(REF)
CT_3_OUT: C90.1 R118.2 ; port CT_3_OUT
CT_4_OUT: C100.1 R134.2 ; port CT_4_OUT
NetC47_1: C47.1 C48.1 R106.2 R107.2 R113.2 U6.3(IN+)
NetC48_2: C48.2 C52.2 R111.1 R112.2 R114.2 U6.2(IN-)
NetC88_1: C88.1 R115.2 R117.1 U14.2(IN_A-)
NetC88_2: C88.2 J28.3 R115.1 TP28.1 U14.1(OUT_A)
NetC94_1: C94.1 C95.1 R122.2 R123.2 R129.2 U15.3(IN+)
NetC95_2: C95.2 C96.2 R127.1 R128.2 R130.2 U15.2(IN-)
NetC99_1: C99.1 R131.2 R133.1 U14.6(IN_B-)
NetC99_2: C99.2 J30.3 R131.1 TP41.1 U14.7(OUT_B)
NetD9_1: D9.1(K) L7.1 R108.2 R110.2 T3.1
NetD9_2: D9.2(K) L8.1 R108.1 R110.1 T3.2
NetD16_1: D16.1(K) L9.1 R124.2 R126.2 T4.1
NetD16_2: D16.2(K) L10.1 R124.1 R126.1 T4.2
NetJ28_1: J28.1 TP8.1 U6.6(OUT)
NetJ28_2: J28.2 R118.1
NetJ30_1: J30.1 TP39.1 U15.6(OUT)
NetJ30_2: J30.2 R134.1
NetL7_2: L7.2 R106.1 TP6.1
NetL8_2: L8.2 R112.1 TP60.1
NetL9_2: L9.2 R122.1 TP38.1
NetL10_2: L10.2 R128.1 TP61.1
NetR109_1: R109.1 U6.1(RG)
NetR109_2: R109.2 U6.8(RG)
NetR113_1: R113.1 R119.2
NetR114_1: R114.1 R116.2 R117.2
NetR119_1: R119.1 R120.2 R121.2 U14.3(IN_A+)
NetR125_1: R125.1 U15.1(RG)
NetR125_2: R125.2 U15.8(RG)
NetR129_1: R129.1 R135.2
NetR130_1: R130.1 R132.1 R133.2
NetR135_1: R135.1 R136.2 R137.2 U14.5(IN_B+)

Not connected (* = marked no-connect by the designer): T3 3 4; T4 3 4

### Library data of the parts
C43 C85 C92 C98 = C1608X5R1C105K: as C12 on sheet TIDA-00834_ISO-E2_Pg3_CT1_CT2
C44 C83 C89 C91 C93 C97 = CGA3E2X8R1E104K080AA: as C13 on sheet TIDA-00834_ISO-E2_Pg3_CT1_CT2
C47 C52 C94 C96 = C0603X102K5RACTU: as C14 on sheet TIDA-00834_ISO-E2_Pg3_CT1_CT2
C48 C95 = 06031C103JAT2A: as C15 on sheet TIDA-00834_ISO-E2_Pg3_CT1_CT2
C88 C90 C99 C100 = 06033C101KAT2A: as C19 on sheet TIDA-00834_ISO-E2_Pg3_CT1_CT2
D9 D16 = PESD3V3L1BA: as D3 on sheet TIDA-00834_ISO-E2_Pg3_CT1_CT2
J28 J30 = 5-146280-3: as J5 on sheet TIDA-00834_ISO-E2_Pg3_CT1_CT2
L7-L10 = FBMJ2125HM210NT: as L1 on sheet TIDA-00834_ISO-E2_Pg3_CT1_CT2
R106 R112 R122 R128 = RT0603BRD07249RL: as R35 on sheet TIDA-00834_ISO-E2_Pg3_CT1_CT2
R107 R111 R120 R121 R123 R127 R136 R137 = RC0603FR-07100KL: as R36 on sheet TIDA-00834_ISO-E2_Pg3_CT1_CT2
R108 R124 = RC0603FR-07169RL: as R37 on sheet TIDA-00834_ISO-E2_Pg3_CT1_CT2
R109 R125 = RG1608P-562-B-T5: as R38 on sheet TIDA-00834_ISO-E2_Pg3_CT1_CT2
R110 R126 = CRCW060315R0FKEA: as R39 on sheet TIDA-00834_ISO-E2_Pg3_CT1_CT2
R113 R114 R116 R129 R130 R132 = RC0603JR-070RL: as R42 on sheet TIDA-00834_ISO-E2_Pg3_CT1_CT2
R115 R131 = RG1608P-823-B-T5: as R43 on sheet TIDA-00834_ISO-E2_Pg3_CT1_CT2
R117 R119 R133 R135 = RC0603FR-078K2L: as R44 on sheet TIDA-00834_ISO-E2_Pg3_CT1_CT2
R118 R134 = CRCW0603100RFKEA: as R45 on sheet TIDA-00834_ISO-E2_Pg3_CT1_CT2
SH-J16 SH-J18 = 881545-2: as SH-J5 on sheet TIDA-00834_ISO-E2_Pg3_CT1_CT2
T3 T4 = CR8350-2500-N: as T1 on sheet TIDA-00834_ISO-E2_Pg3_CT1_CT2
TP6 TP38 TP60 TP61 = 1573-2: as TP5 on sheet TIDA-00834_ISO-E2_Pg3_CT1_CT2
TP8 TP39 = 5002: as TP7 on sheet TIDA-00834_ISO-E2_Pg3_CT1_CT2
TP26 TP40 = 5001: as TP9 on sheet TIDA-00834_ISO-E2_Pg3_CT1_CT2
TP28 TP41 = TP-040_RND: as TP10 on sheet TIDA-00834_ISO-E2_Pg3_CT1_CT2
U6 U15 = INA188D: as U3 on sheet TIDA-00834_ISO-E2_Pg3_CT1_CT2
U14 = OPA2188AID: as U4 on sheet TIDA-00834_ISO-E2_Pg3_CT1_CT2

## Sheet TIDA-00834_ISO-E2_Pg5_VOLTAGE.SchDoc: VOLATGE1,VOLTAGE2  WITH ISOLATION AMPLIFIER
size 431 x 279 mm; Date: Not shown in title block; ApprovedBy: Not shown in title block; CheckedBy: Not shown in title block; Author: Not shown in title block; CompanyName: Not shown in title block; DrawnBy: Sreenivasa; Engineer: Not shown in title block; Organization: Not shown in title block; Address1: Not shown in title block; Address2: Not shown in title block; Address3: Not shown in title block; Address4: Not shown in title block; DocumentNumber: 1; Revision: Use project parameter SCH_Rev; SheetNumber: 5; SheetTotal: 12; PageSetup: Record=PageOptions¦CenterHorizontal=True¦CenterVertical=True¦PrintScale=1.00¦XCorrection=1.00¦YCorrection=1.00¦PrintKind=0¦BorderSize=5000000¦LeftOffset=0¦BottomOffset=0¦Orientation=2¦PaperLength=1000¦PaperWidth=1000¦Scale=100¦PaperSource=15¦PrintQuality=600¦MediaType=1¦DitherType=10¦PaperKind=Letter¦PrintScaleMode=1
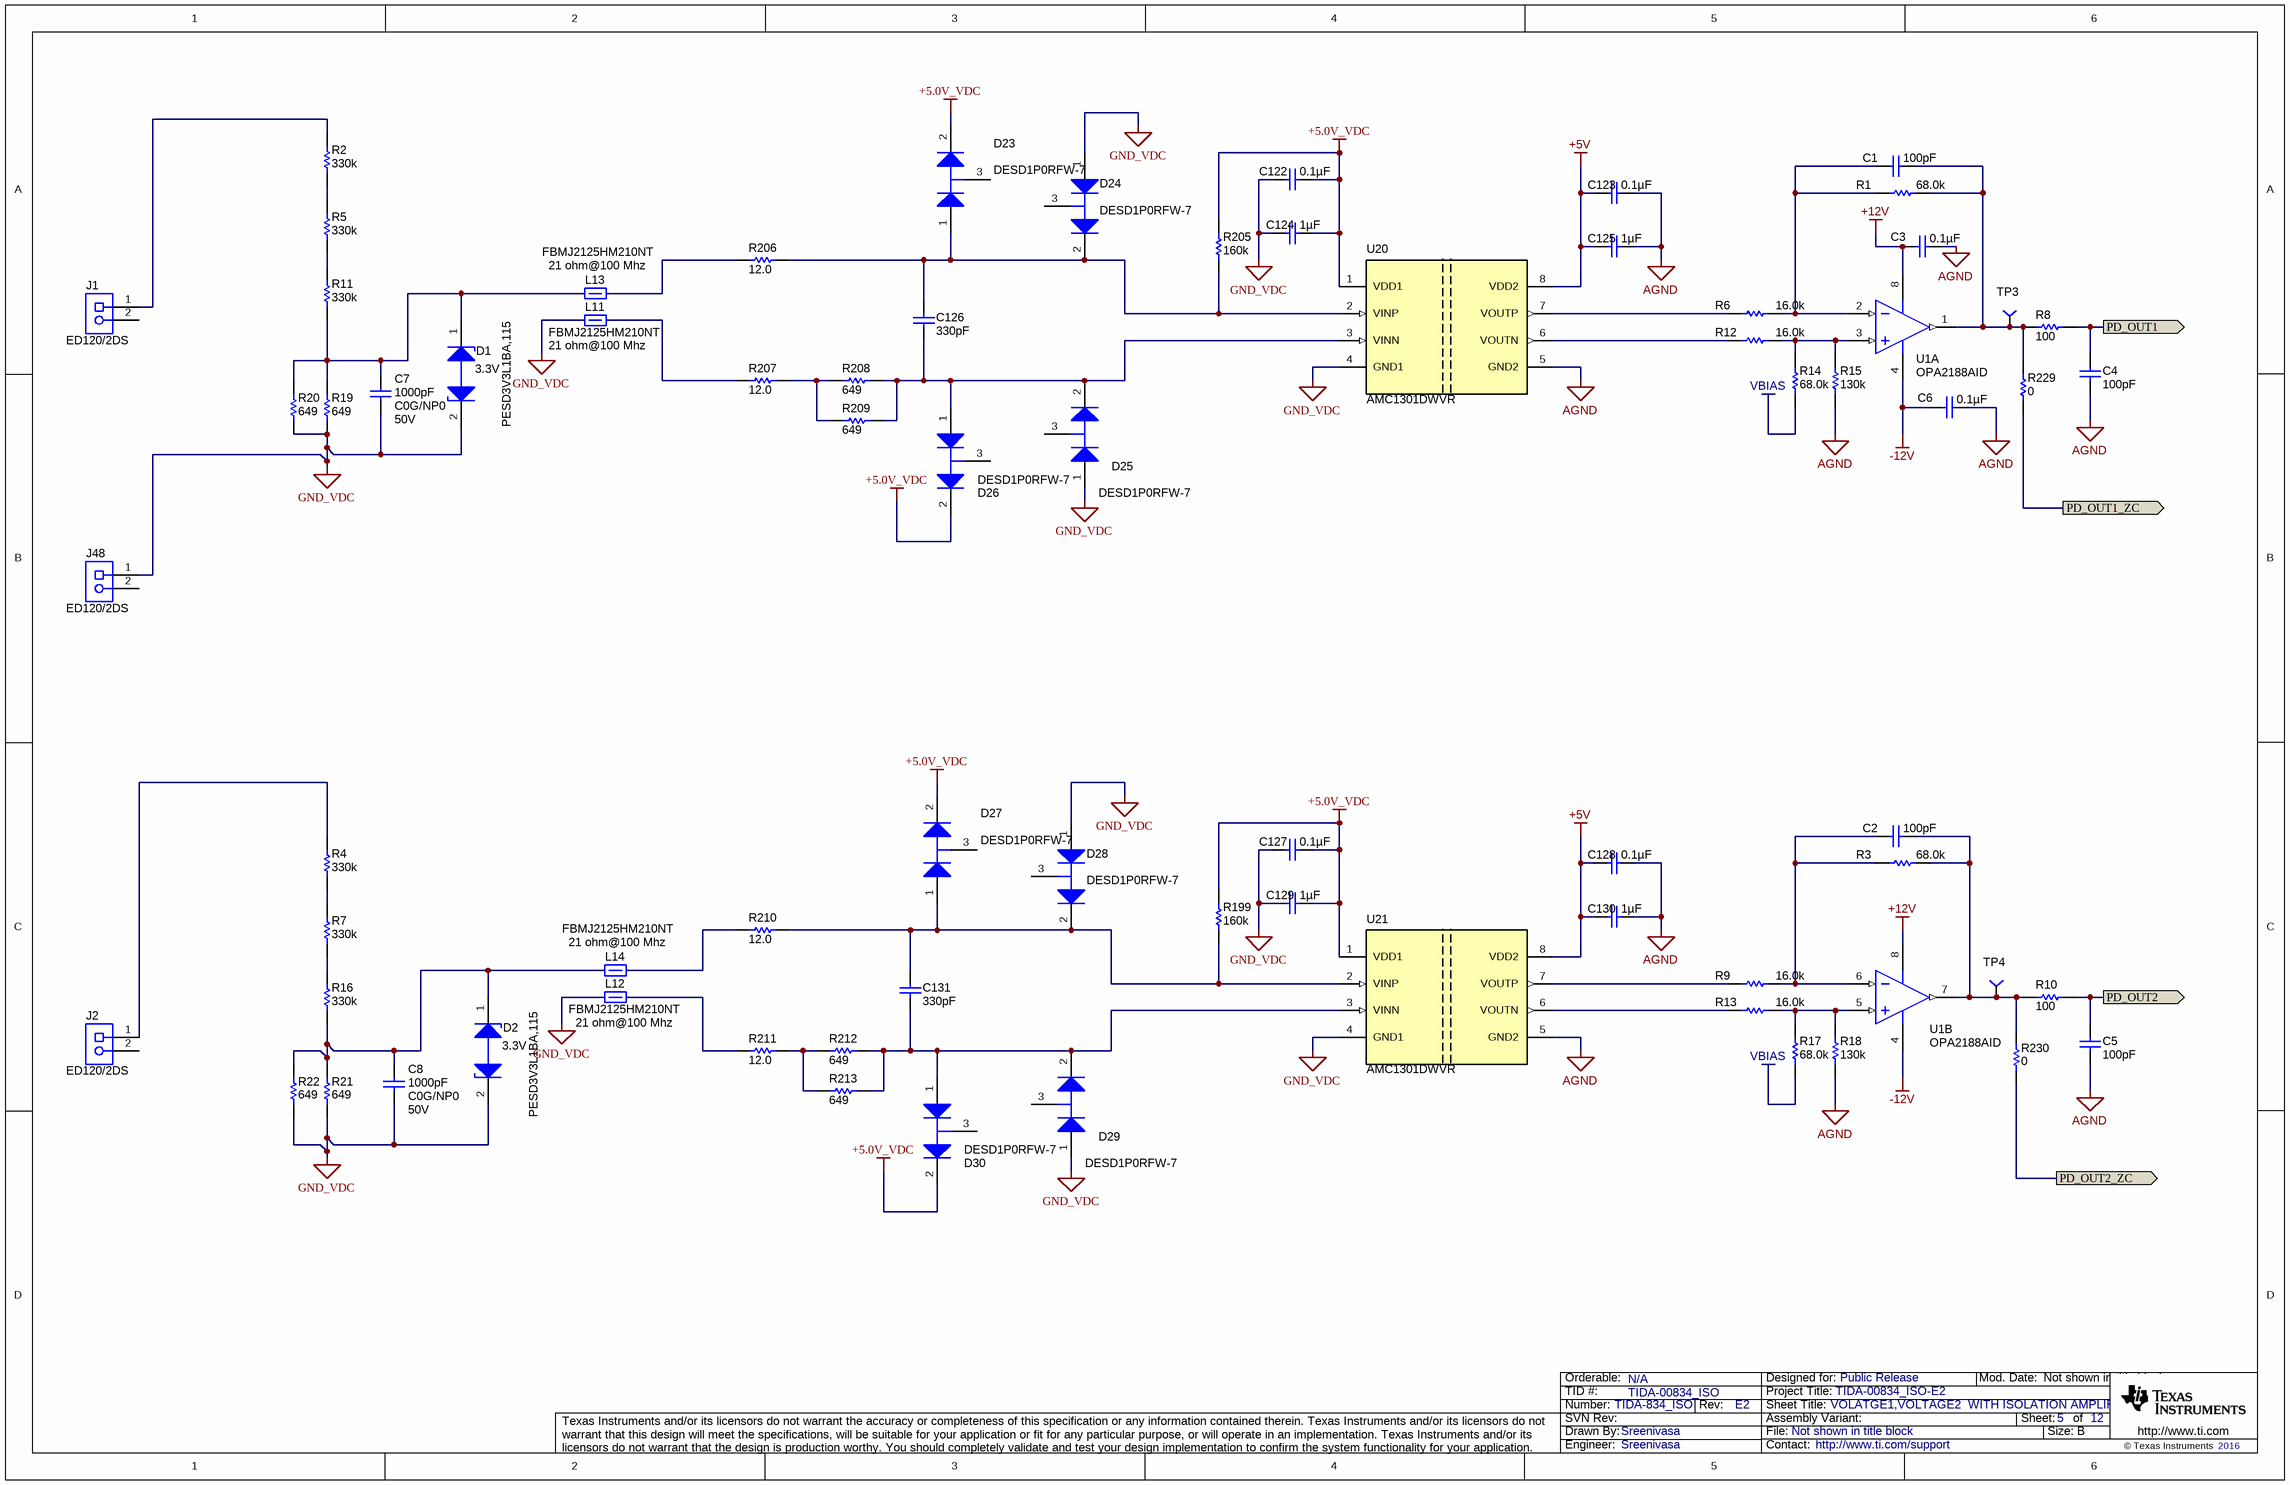
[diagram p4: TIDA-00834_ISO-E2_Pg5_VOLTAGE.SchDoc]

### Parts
C1  ValueDisplayed: 100pF  [0603]  (hidden comment: 06033C101KAT2A)
C2  ValueDisplayed: 100pF  [0603]  (hidden comment: 06033C101KAT2A)
C3  ValueDisplayed: 0.1µF  [0603]  (hidden comment: 06033C104JAT2A)
C4  ValueDisplayed: 100pF  [0603]  (hidden comment: 06033C101KAT2A)
C5  ValueDisplayed: 100pF  [0603]  (hidden comment: 06033C101KAT2A)
C6  ValueDisplayed: 0.1µF  [0603]  (hidden comment: 06033C104JAT2A)
C7  ValueDisplayed: 1000pF  Value2: 50V  TempCo: C0G/NP0  [0603]  (hidden comment: C1608C0G1H102J080AA)
C8  ValueDisplayed: 1000pF  Value2: 50V  TempCo: C0G/NP0  [0603]  (hidden comment: C1608C0G1H102J080AA)
C122  ValueDisplayed: 0.1µF  [0603]
C123  ValueDisplayed: 0.1µF  [0603]
C124  ValueDisplayed: 1µF  [0603]  (hidden comment: GRM188R71C105KA12D)
C125  ValueDisplayed: 1µF  [0603]  (hidden comment: GRM188R71C105KA12D)
C126  ValueDisplayed: 330pF  [0805_HV]  (hidden comment: 08055A331KAT2A)
C127  ValueDisplayed: 0.1µF  [0603]
C128  ValueDisplayed: 0.1µF  [0603]
C129  ValueDisplayed: 1µF  [0603]  (hidden comment: GRM188R71C105KA12D)
C130  ValueDisplayed: 1µF  [0603]  (hidden comment: GRM188R71C105KA12D)
C131  ValueDisplayed: 330pF  [0805_HV]  (hidden comment: 08055A331KAT2A)
D1  PESD3V3L1BA,115  value 3.3V  [DIO_SOD323]
D2  PESD3V3L1BA,115  value 3.3V  [DIO_SOD323]
D23  value DESD1P0RFW-7  [SOT-323]
D24  value DESD1P0RFW-7  [SOT-323]
D25  value DESD1P0RFW-7  [SOT-323]
D26  value DESD1P0RFW-7  [SOT-323]
D27  value DESD1P0RFW-7  [SOT-323]
D28  value DESD1P0RFW-7  [SOT-323]
D29  value DESD1P0RFW-7  [SOT-323]
D30  value DESD1P0RFW-7  [SOT-323]
J1  ED120/2DS  [CONN_ED120-2DS]
J2  ED120/2DS  [CONN_ED120-2DS]
J48  ED120/2DS  [CONN_ED120-2DS]
L11  value 21 ohm@100 Mhz  [0805_HV]  (hidden comment: FBMJ2125HM210NT)
L12  value 21 ohm@100 Mhz  [0805_HV]  (hidden comment: FBMJ2125HM210NT)
L13  value 21 ohm@100 Mhz  [0805_HV]  (hidden comment: FBMJ2125HM210NT)
L14  value 21 ohm@100 Mhz  [0805_HV]  (hidden comment: FBMJ2125HM210NT)
R1  ValueDisplayed: 68.0k  [0603]  (hidden comment: RC0603FR-0768KL)
R2  ValueDisplayed: 330k  [1206]  (hidden comment: RC1206FR-07330KL)
R3  ValueDisplayed: 68.0k  [0603]  (hidden comment: RC0603FR-0768KL)
R4  ValueDisplayed: 330k  [1206]  (hidden comment: RC1206FR-07330KL)
R5  ValueDisplayed: 330k  [1206]  (hidden comment: RC1206FR-07330KL)
R6  ValueDisplayed: 16.0k  [0603]  (hidden comment: RC0603FR-0716KL)
R7  ValueDisplayed: 330k  [1206]  (hidden comment: RC1206FR-07330KL)
R8  value 100  [0603]  (hidden comment: CRCW0603100RFKEA)
R9  ValueDisplayed: 16.0k  [0603]  (hidden comment: RC0603FR-0716KL)
R10  value 100  [0603]  (hidden comment: CRCW0603100RFKEA)
R11  ValueDisplayed: 330k  [1206]  (hidden comment: RC1206FR-07330KL)
R12  ValueDisplayed: 16.0k  [0603]  (hidden comment: RC0603FR-0716KL)
R13  ValueDisplayed: 16.0k  [0603]  (hidden comment: RC0603FR-0716KL)
R14  ValueDisplayed: 68.0k  [0603]  (hidden comment: RC0603FR-0768KL)
R15  ValueDisplayed: 130k  [0603]  (hidden comment: CRCW0603130KFKEA)
R16  ValueDisplayed: 330k  [1206]  (hidden comment: RC1206FR-07330KL)
R17  ValueDisplayed: 68.0k  [0603]  (hidden comment: RC0603FR-0768KL)
R18  ValueDisplayed: 130k  [0603]  (hidden comment: CRCW0603130KFKEA)
R19  ValueDisplayed: 649  [0603]  (hidden comment: CRCW0603649RFKEA)
R20  ValueDisplayed: 649  [0603]  (hidden comment: CRCW0603649RFKEA)
R21  ValueDisplayed: 649  [0603]  (hidden comment: CRCW0603649RFKEA)
R22  ValueDisplayed: 649  [0603]  (hidden comment: CRCW0603649RFKEA)
R199  ValueDisplayed: 160k  [0603]  (hidden comment: CRCW0603160KFKEA)
R205  ValueDisplayed: 160k  [0603]  (hidden comment: CRCW0603160KFKEA)
R206  ValueDisplayed: 12.0  [0603]  (hidden comment: RC0603FR-0712RL)
R207  ValueDisplayed: 12.0  [0603]  (hidden comment: RC0603FR-0712RL)
R208  ValueDisplayed: 649  [0603]  (hidden comment: CRCW0603649RFKEA)
R209  ValueDisplayed: 649  [0603]  (hidden comment: CRCW0603649RFKEA)
R210  ValueDisplayed: 12.0  [0603]  (hidden comment: RC0603FR-0712RL)
R211  ValueDisplayed: 12.0  [0603]  (hidden comment: RC0603FR-0712RL)
R212  ValueDisplayed: 649  [0603]  (hidden comment: CRCW0603649RFKEA)
R213  ValueDisplayed: 649  [0603]  (hidden comment: CRCW0603649RFKEA)
R229  ValueDisplayed: 0  [0603]  (hidden comment: RC0603JR-070RL)
R230  ValueDisplayed: 0  [0603]  (hidden comment: RC0603JR-070RL)
TP3  TP-040_RND  [TP_H045P075]  (value not drawn)
TP4  TP-040_RND  [TP_H045P075]  (value not drawn)
U1  OPA2188AID  [D0008A_N]  (parts A,B of 2)
U20  AMC1301DWVR  [DWV0008A]
U21  AMC1301DWVR  [DWV0008A]

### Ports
PD_OUT1 (out), PD_OUT1_ZC (out), PD_OUT2 (out), PD_OUT2_ZC (out)

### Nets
+5.0V_VDC: C122.1 C124.2 C127.1 C129.2 D23.2(K) D26.2(K) D27.2(K) D30.2(K) R199.2 R205.2 U20.1(VDD1) U21.1(VDD1)
+5V: C123.2 C125.1 C128.2 C130.1 U20.8(VDD2) U21.8(VDD2)
+12V: C3.2 U1.8(V+)
-12V: C6.2 U1.4(V-)
AGND: C3.1 C4.2 C5.2 C6.1 C123.1 C125.2 C128.1 C130.2 R15.1 R18.1 U20.5(GND2) U21.5(GND2)
GND_VDC: C7.1 C8.1 C122.2 C124.1 C127.2 C129.1 D1.2(K) D2.2(K) D24.1(A) D25.1(A) D28.1(A) D29.1(A) J48.1 L11.1 L12.1 R19.1 R20.1 R21.1 R22.1 U20.4(GND1) U21.4(GND1)
VBIAS: R14.1 R17.1
PD_OUT1: C4.1 R8.2 ; port PD_OUT1
PD_OUT1_ZC: R229.1 ; port PD_OUT1_ZC
PD_OUT2: C5.1 R10.2 ; port PD_OUT2
PD_OUT2_ZC: R230.1 ; port PD_OUT2_ZC
NetC1_1: C1.1 R1.2 R6.1 U1.2(IN_A-)
NetC1_2: C1.2 R1.1 R8.1 R229.2 TP3.1 U1.1(OUT_A)
NetC2_1: C2.1 R3.2 R9.1 U1.6(IN_B-)
NetC2_2: C2.2 R3.1 R10.1 R230.2 TP4.1 U1.7(OUT_B)
NetC7_2: C7.2 D1.1(K) L13.1 R11.1 R19.2 R20.2
NetC8_2: C8.2 D2.1(K) L14.1 R16.1 R21.2 R22.2
NetC126_1: C126.1 D23.1(A) D24.2(K) R205.1 R206.2 U20.2(VINP)
NetC126_2: C126.2 D25.2(K) D26.1(A) R208.1 R209.1 U20.3(VINN)
NetC131_1: C131.1 D27.1(A) D28.2(K) R199.1 R210.2 U21.2(VINP)
NetC131_2: C131.2 D29.2(K) D30.1(A) R212.1 R213.1 U21.3(VINN)
NetJ1_1: J1.1 R2.2
NetJ2_1: J2.1 R4.2
NetL11_2: L11.2 R207.1
NetL12_2: L12.2 R211.1
NetL13_2: L13.2 R206.1
NetL14_2: L14.2 R210.1
NetR2_1: R2.1 R5.2
NetR4_1: R4.1 R7.2
NetR5_1: R5.1 R11.2
NetR6_2: R6.2 U20.7(VOUTP)
NetR7_1: R7.1 R16.2
NetR9_2: R9.2 U21.7(VOUTP)
NetR12_1: R12.1 R14.2 R15.2 U1.3(IN_A+)
NetR12_2: R12.2 U20.6(VOUTN)
NetR13_1: R13.1 R17.2 R18.2 U1.5(IN_B+)
NetR13_2: R13.2 U21.6(VOUTN)
NetR207_2: R207.2 R208.2 R209.2
NetR211_2: R211.2 R212.2 R213.2

Not connected (* = marked no-connect by the designer): D23 3(C); D24 3(C); D25 3(C); D26 3(C); D27 3(C); D28 3(C); D29 3(C); D30 3(C); J1 2; J2 2; J48 2

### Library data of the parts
C1 C2 C4 C5 = 06033C101KAT2A: as C19 on sheet TIDA-00834_ISO-E2_Pg3_CT1_CT2
C3 C6 C122 C123 C127 C128 = 06033C104JAT2A: CAP, CERM, 0.1uF, 25V, +/-5%, X7R, 0603; Manufacturer: AVX; Polarized: N; CompType: Capacitor; U/M: EA; Cap_F: 0.0000001; Tolerance_%: 5; ESR_Ohm: 0.05; Value1: 0.05 ohm; VDC_V: 25; TaMin_C: -55; TaMax_C: 125
C7 C8 = C1608C0G1H102J: CAP, CERM, 1000pF, 50V, +/-5%, C0G/NP0, 0603; Manufacturer: TDK; Polarized: N; CompType: Capacitor; U/M: EA; Cap_F: 0.000000001; Tolerance_%: 5; ESR_Ohm: 0.0563; Value1: 0.0563 ohm; VDC_V: 50; TaMin_C: -55; TaMax_C: 125
C124 C125 C129 C130 = GRM188R71C105KA12D: CAP, CERM, 1 µF, 16 V, +/- 10%, X7R, 0603; Manufacturer: MuRata; Polarized: N; CompType: Capacitor; Value: 1uF; U/M: EA; Cap_F: 0.000001; Tolerance_%: 10; ESR_ohm: 0.011; Value1: 0.011 ohm; VDC_V: 16; Value2: 16V; TaMin_C: -55; TaMax_C: 125
C126 C131 = 08055A331KAT2A: CAP, CERM, 330 pF, 50 V, +/- 10%, C0G/NP0, 0805; Manufacturer: AVX; Polarized: N; CompType: Capacitor; Value: 330pF; U/M: EA; Cap_F: 0.00000000033; Tolerance_%: 10; ESR_ohm: 0.189; Value1: 0.189 ohm; VDC_V: 50; Value2: 50V; TaMin_C: -55; TaMax_C: 125; Cap_Case: 0805
D1 D2 = PESD3V3L1BA: as D3 on sheet TIDA-00834_ISO-E2_Pg3_CT1_CT2
D23-D30 = BAV99WT1G: Diode, P-N, 70V, 0.2A, SOT-323; Manufacturer: Diodes Inc
J1 J2 J48 = ED120/2DS: TERMINAL BLOCK 5.08MM VERT 2POS, TH; Manufacturer: On-Shore Technology; SymbolCreator: a0412235; U/M: EA
L11-L14 = FBMJ2125HM210NT: as L1 on sheet TIDA-00834_ISO-E2_Pg3_CT1_CT2
R1 R3 R14 R17 = RC0603FR-0768KL: RES, 68.0 k, 1%, 0.1 W, 0603; Manufacturer: Yageo America; CompType: Resistor; Value: 68.0k; Res_ohm: 68000; Value_Code: 68k0; Tolerance_%: 1; Power_W: 0.1; Value2: 0.1W; VDC_V: 150; TempCo: 200 ppm/C; SizeArea_mm2: 1.28; SizeX_mm: 1.6; SizeY_mm: 0.8; U/M: EA; AEC Category: Q200
R2 R4 R5 R7 R11 R16 = RC1206FR-07330KL: RES, 330 k, 1%, 0.25 W, 1206; Manufacturer: Yageo America; CompType: Resistor; Value: 330k; Res_ohm: 330000; Tolerance_%: 1; Power_W: 0.25; Value2: 0.25W; VDC_V: 200; TempCo: 100 ppm/C; U/M: EA
R6 R9 R12 R13 = RC0603FR-0716KL: RES, 16.0 k, 1%, 0.1 W, 0603; Manufacturer: Yageo America; CompType: Resistor; Value: 16.0k; Res_ohm: 16000; Value_Code: 16k0; Tolerance_%: 1; Power_W: 0.1; Value2: 0.1W; VDC_V: 150; TempCo: 200 ppm/C; SizeArea_mm2: 1.28; SizeX_mm: 1.6; SizeY_mm: 0.8; U/M: EA; AEC Category: Q200
R8 R10 = CRCW0603100RFKEA: as R45 on sheet TIDA-00834_ISO-E2_Pg3_CT1_CT2
R15 R18 = CRCW0603130KFKEA: RES, 130 k, 1%, 0.1 W, 0603; Manufacturer: Vishay-Dale; CompType: Resistor; Value: 130k; Res_ohm: 130000; Tolerance_%: 1; Power_W: 0.1; Value2: 0.1W; VDC_V: 75; TempCo: 100 ppm/C; SizeArea_mm2: 1.28; SizeX_mm: 1.6; SizeY_mm: 0.8; EIA_Code: E96; U/M: EA; AEC Category: Q200
R19-R22 R208 R209 R212 R213 = CRCW0603649RFKEA: RES, 649, 1%, 0.1 W, 0603; Manufacturer: Vishay-Dale; CompType: Resistor; Value: 649; Value_Code: 649R; Tolerance_%: 1; Power_W: 0.1; Value2: 0.1W; VDC_V: 75; TempCo: 100 ppm/C; EIA_Code: E96; U/M: EA; AEC Category: Q200
R199 R205 = CRCW0603160KFKEA: RES, 160 k, 1%, 0.1 W, 0603; Manufacturer: Vishay-Dale; CompType: Resistor; Value: 160k; Res_ohm: 160000; Tolerance_%: 1; Power_W: 0.1; Value2: 0.1W; VDC_V: 75; TempCo: 100 ppm/C; U/M: EA
R206 R207 R210 R211 = RC0603FR-0712RL: RES, 12.0, 1%, 0.1 W, 0603; Manufacturer: Yageo America; CompType: Resistor; Value: 12.0; Res_ohm: 12; Value_Code: 12R0; Tolerance_%: 1; Power_W: 0.1; Value2: 0.1W; VDC_V: 150; TempCo: 200 ppm/C; U/M: EA
R229 R230 = RC0603JR-070RL: as R42 on sheet TIDA-00834_ISO-E2_Pg3_CT1_CT2
TP3 TP4 = TP-040_RND: as TP10 on sheet TIDA-00834_ISO-E2_Pg3_CT1_CT2
U1 = OPA2188AID: as U4 on sheet TIDA-00834_ISO-E2_Pg3_CT1_CT2
U20 U21 = AMC1301DWVR: 200 kHz, Fully-Differential Isolation Amplifier, DWV0008A; Manufacturer: Texas Instruments; SymbolCreator: Altium; CompType: IC; U/M: EA

## Sheet TIDA-00834_ISO-E2_Pg6_VOLTAGE2.SchDoc: VOLATGE3, VOLTAGE4  WITH ISOLATION AMPLIFIER
size 431 x 279 mm; Date: Not shown in title block; ApprovedBy: Not shown in title block; CheckedBy: Not shown in title block; Author: Not shown in title block; CompanyName: Not shown in title block; DrawnBy: Sreenivasa; Engineer: Not shown in title block; Organization: Not shown in title block; Address1: Not shown in title block; Address2: Not shown in title block; Address3: Not shown in title block; Address4: Not shown in title block; DocumentNumber: 1; Revision: Use project parameter SCH_Rev; SheetNumber: 6; SheetTotal: 12; PageSetup: Record=PageOptions¦CenterHorizontal=True¦CenterVertical=True¦PrintScale=1.00¦XCorrection=1.00¦YCorrection=1.00¦PrintKind=0¦BorderSize=5000000¦LeftOffset=0¦BottomOffset=0¦Orientation=2¦PaperLength=1000¦PaperWidth=1000¦Scale=100¦PaperSource=15¦PrintQuality=600¦MediaType=1¦DitherType=10¦PaperKind=Letter¦PrintScaleMode=1
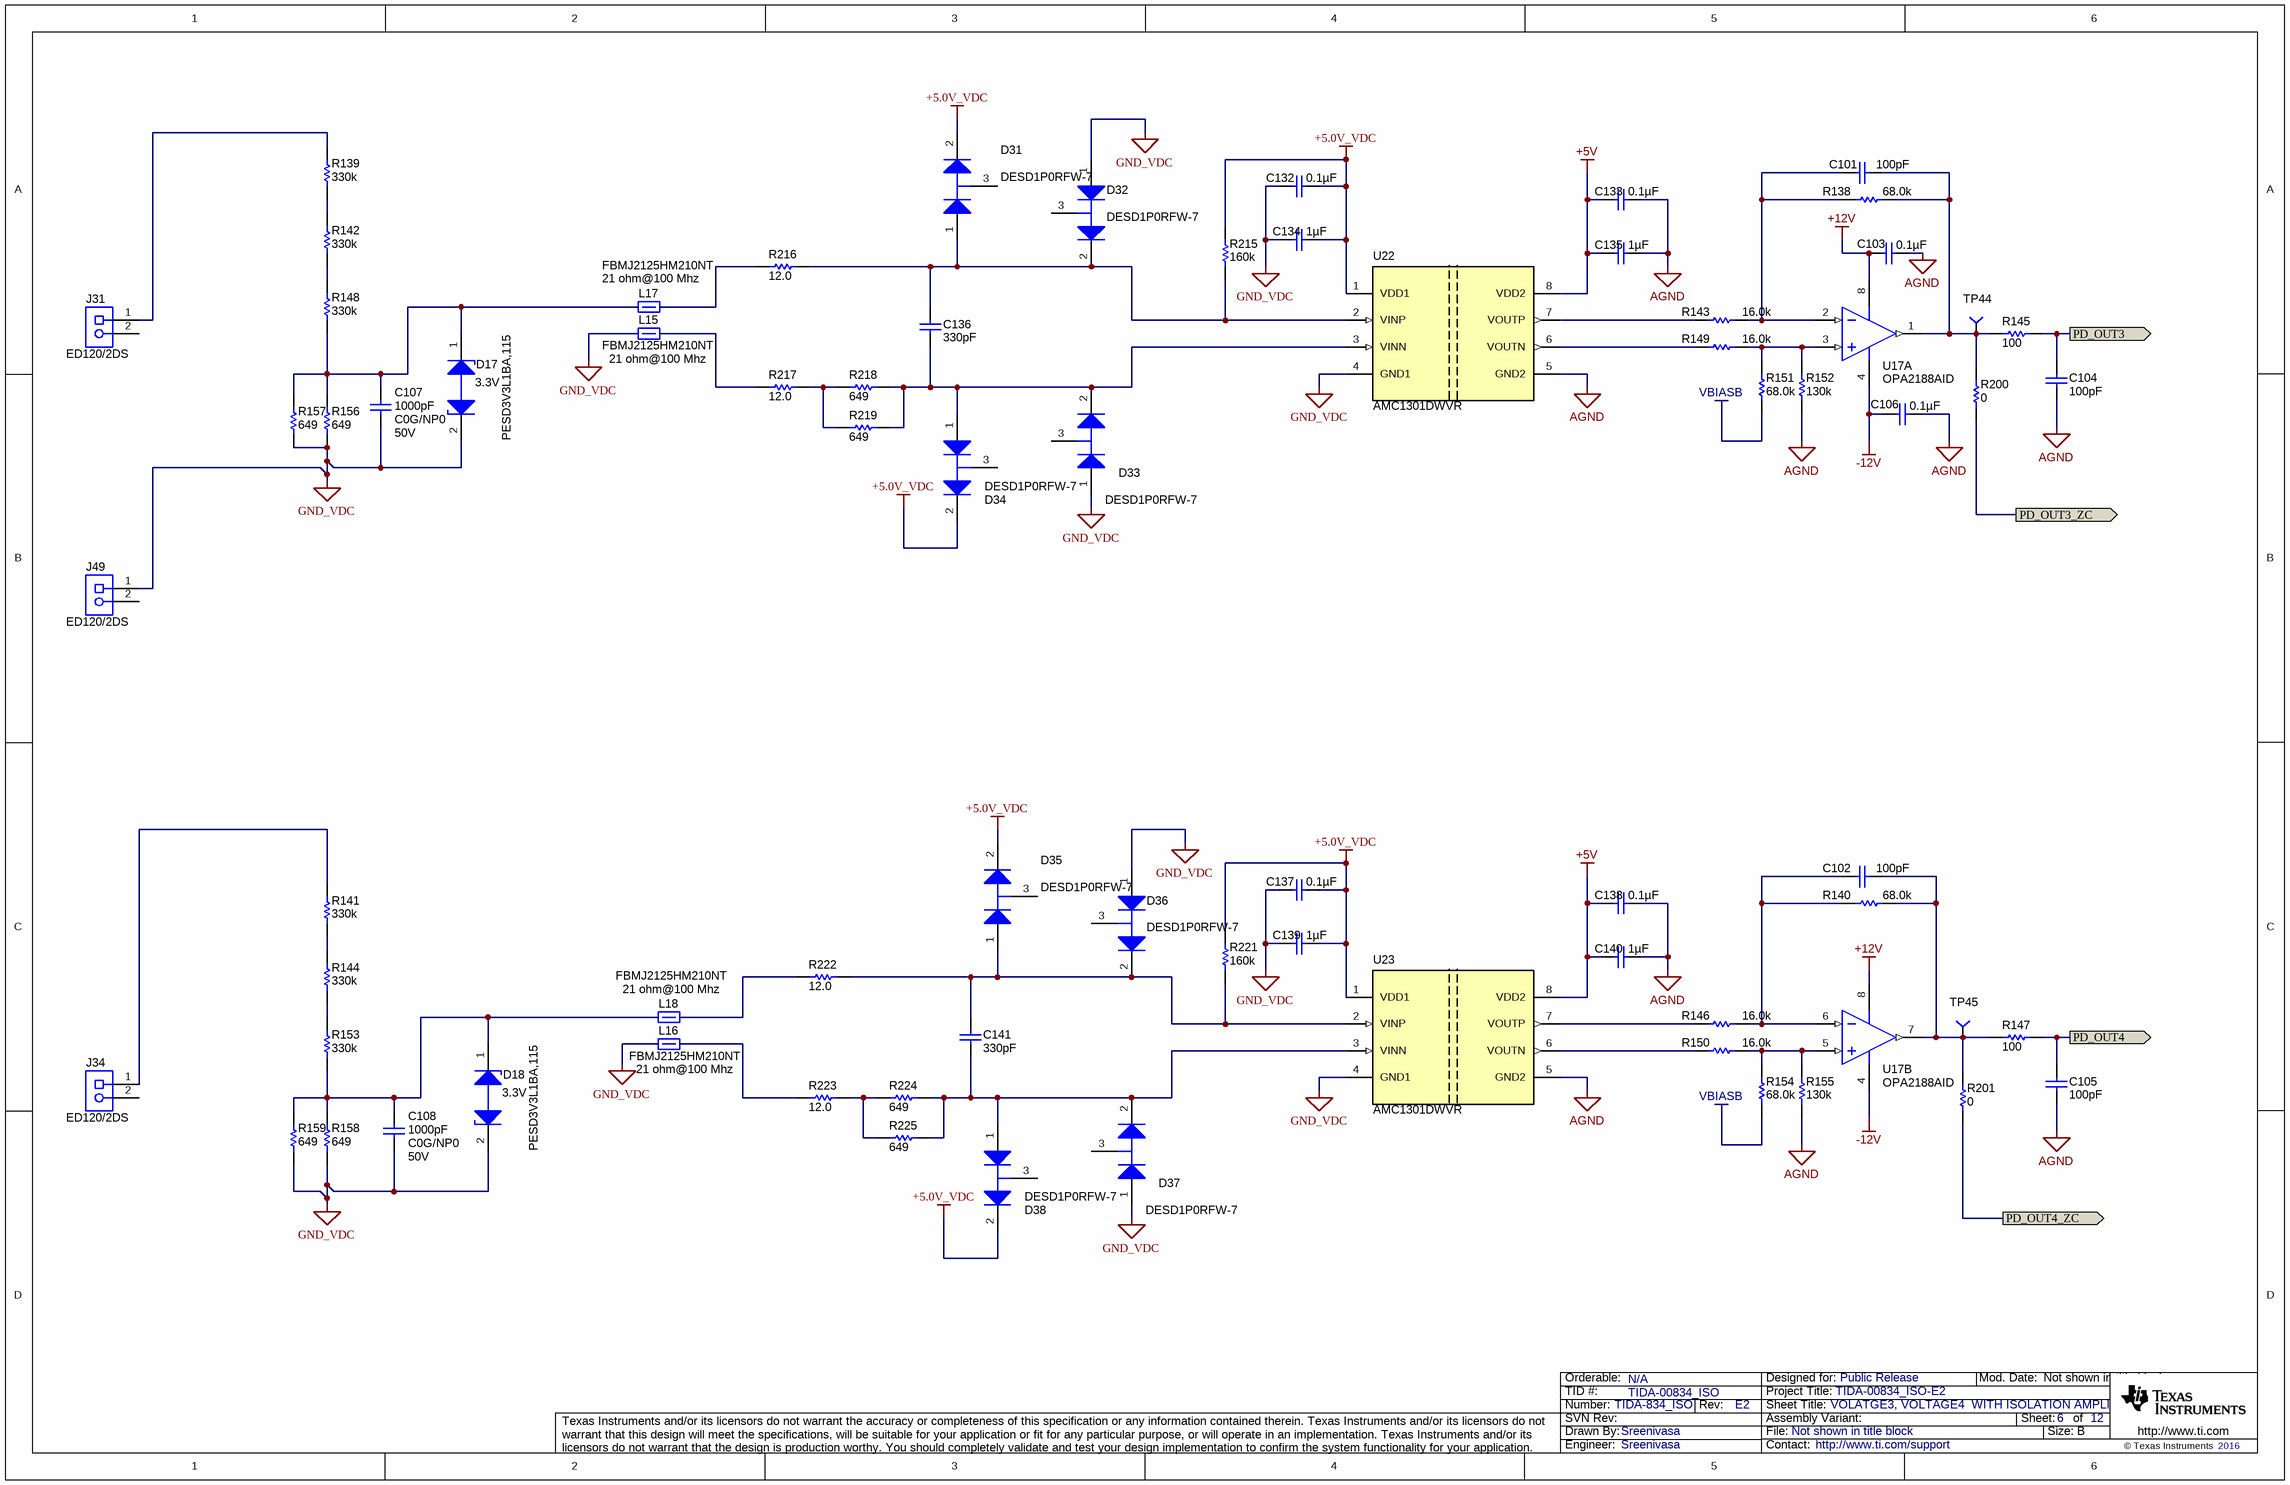
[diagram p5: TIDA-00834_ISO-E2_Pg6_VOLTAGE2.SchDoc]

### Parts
C101  ValueDisplayed: 100pF  [0603]  (hidden comment: 06033C101KAT2A)
C102  ValueDisplayed: 100pF  [0603]  (hidden comment: 06033C101KAT2A)
C103  ValueDisplayed: 0.1µF  [0603]  (hidden comment: 06033C104JAT2A)
C104  ValueDisplayed: 100pF  [0603]  (hidden comment: 06033C101KAT2A)
C105  ValueDisplayed: 100pF  [0603]  (hidden comment: 06033C101KAT2A)
C106  ValueDisplayed: 0.1µF  [0603]  (hidden comment: 06033C104JAT2A)
C107  ValueDisplayed: 1000pF  Value2: 50V  TempCo: C0G/NP0  [0603]  (hidden comment: C1608C0G1H102J080AA)
C108  ValueDisplayed: 1000pF  Value2: 50V  TempCo: C0G/NP0  [0603]  (hidden comment: C1608C0G1H102J080AA)
C132  ValueDisplayed: 0.1µF  [0603]
C133  ValueDisplayed: 0.1µF  [0603]
C134  ValueDisplayed: 1µF  [0603]  (hidden comment: GRM188R71C105KA12D)
C135  ValueDisplayed: 1µF  [0603]  (hidden comment: GRM188R71C105KA12D)
C136  ValueDisplayed: 330pF  [0805_HV]  (hidden comment: 08055A331KAT2A)
C137  ValueDisplayed: 0.1µF  [0603]
C138  ValueDisplayed: 0.1µF  [0603]
C139  ValueDisplayed: 1µF  [0603]  (hidden comment: GRM188R71C105KA12D)
C140  ValueDisplayed: 1µF  [0603]  (hidden comment: GRM188R71C105KA12D)
C141  ValueDisplayed: 330pF  [0805_HV]  (hidden comment: 08055A331KAT2A)
D17  PESD3V3L1BA,115  value 3.3V  [DIO_SOD323]
D18  PESD3V3L1BA,115  value 3.3V  [DIO_SOD323]
D31  value DESD1P0RFW-7  [SOT-323]
D32  value DESD1P0RFW-7  [SOT-323]
D33  value DESD1P0RFW-7  [SOT-323]
D34  value DESD1P0RFW-7  [SOT-323]
D35  value DESD1P0RFW-7  [SOT-323]
D36  value DESD1P0RFW-7  [SOT-323]
D37  value DESD1P0RFW-7  [SOT-323]
D38  value DESD1P0RFW-7  [SOT-323]
J31  ED120/2DS  [CONN_ED120-2DS]
J34  ED120/2DS  [CONN_ED120-2DS]
J49  ED120/2DS  [CONN_ED120-2DS]
L15  value 21 ohm@100 Mhz  [0805_HV]  (hidden comment: FBMJ2125HM210NT)
L16  value 21 ohm@100 Mhz  [0805_HV]  (hidden comment: FBMJ2125HM210NT)
L17  value 21 ohm@100 Mhz  [0805_HV]  (hidden comment: FBMJ2125HM210NT)
L18  value 21 ohm@100 Mhz  [0805_HV]  (hidden comment: FBMJ2125HM210NT)
R138  ValueDisplayed: 68.0k  [0603]  (hidden comment: RC0603FR-0768KL)
R139  ValueDisplayed: 330k  [1206]  (hidden comment: RC1206FR-07330KL)
R140  ValueDisplayed: 68.0k  [0603]  (hidden comment: RC0603FR-0768KL)
R141  ValueDisplayed: 330k  [1206]  (hidden comment: RC1206FR-07330KL)
R142  ValueDisplayed: 330k  [1206]  (hidden comment: RC1206FR-07330KL)
R143  ValueDisplayed: 16.0k  [0603]  (hidden comment: RC0603FR-0716KL)
R144  ValueDisplayed: 330k  [1206]  (hidden comment: RC1206FR-07330KL)
R145  value 100  [0603]  (hidden comment: CRCW0603100RFKEA)
R146  ValueDisplayed: 16.0k  [0603]  (hidden comment: RC0603FR-0716KL)
R147  value 100  [0603]  (hidden comment: CRCW0603100RFKEA)
R148  ValueDisplayed: 330k  [1206]  (hidden comment: RC1206FR-07330KL)
R149  ValueDisplayed: 16.0k  [0603]  (hidden comment: RC0603FR-0716KL)
R150  ValueDisplayed: 16.0k  [0603]  (hidden comment: RC0603FR-0716KL)
R151  ValueDisplayed: 68.0k  [0603]  (hidden comment: RC0603FR-0768KL)
R152  ValueDisplayed: 130k  [0603]  (hidden comment: CRCW0603130KFKEA)
R153  ValueDisplayed: 330k  [1206]  (hidden comment: RC1206FR-07330KL)
R154  ValueDisplayed: 68.0k  [0603]  (hidden comment: RC0603FR-0768KL)
R155  ValueDisplayed: 130k  [0603]  (hidden comment: CRCW0603130KFKEA)
R156  ValueDisplayed: 649  [0603]  (hidden comment: CRCW0603649RFKEA)
R157  ValueDisplayed: 649  [0603]  (hidden comment: CRCW0603649RFKEA)
R158  ValueDisplayed: 649  [0603]  (hidden comment: CRCW0603649RFKEA)
R159  ValueDisplayed: 649  [0603]  (hidden comment: CRCW0603649RFKEA)
R200  ValueDisplayed: 0  [0603]  (hidden comment: RC0603JR-070RL)
R201  ValueDisplayed: 0  [0603]  (hidden comment: RC0603JR-070RL)
R215  ValueDisplayed: 160k  [0603]  (hidden comment: CRCW0603160KFKEA)
R216  ValueDisplayed: 12.0  [0603]  (hidden comment: RC0603FR-0712RL)
R217  ValueDisplayed: 12.0  [0603]  (hidden comment: RC0603FR-0712RL)
R218  ValueDisplayed: 649  [0603]  (hidden comment: CRCW0603649RFKEA)
R219  ValueDisplayed: 649  [0603]  (hidden comment: CRCW0603649RFKEA)
R221  ValueDisplayed: 160k  [0603]  (hidden comment: CRCW0603160KFKEA)
R222  ValueDisplayed: 12.0  [0603]  (hidden comment: RC0603FR-0712RL)
R223  ValueDisplayed: 12.0  [0603]  (hidden comment: RC0603FR-0712RL)
R224  ValueDisplayed: 649  [0603]  (hidden comment: CRCW0603649RFKEA)
R225  ValueDisplayed: 649  [0603]  (hidden comment: CRCW0603649RFKEA)
TP44  TP-040_RND  [TP_H045P075]  (value not drawn)
TP45  TP-040_RND  [TP_H045P075]  (value not drawn)
U17  OPA2188AID  [D0008A_N]  (parts A,B of 2)
U22  AMC1301DWVR  [DWV0008A]
U23  AMC1301DWVR  [DWV0008A]

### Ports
PD_OUT3 (out), PD_OUT3_ZC (out), PD_OUT4 (out), PD_OUT4_ZC (out)

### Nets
+5.0V_VDC: C132.1 C134.2 C137.1 C139.2 D31.2(K) D34.2(K) D35.2(K) D38.2(K) R215.2 R221.2 U22.1(VDD1) U23.1(VDD1)
+5V: C133.2 C135.1 C138.2 C140.1 U22.8(VDD2) U23.8(VDD2)
+12V: C103.2 U17.8(V+)
-12V: C106.2 U17.4(V-)
AGND: C103.1 C104.2 C105.2 C106.1 C133.1 C135.2 C138.1 C140.2 R152.1 R155.1 U22.5(GND2) U23.5(GND2)
GND_VDC: C107.1 C108.1 C132.2 C134.1 C137.2 C139.1 D17.2(K) D18.2(K) D32.1(A) D33.1(A) D36.1(A) D37.1(A) J49.1 L15.1 L16.1 R156.1 R157.1 R158.1 R159.1 U22.4(GND1) U23.4(GND1)
VBIASB: R151.1 R154.1
PD_OUT3: C104.1 R145.2 ; port PD_OUT3
PD_OUT3_ZC: R200.1 ; port PD_OUT3_ZC
PD_OUT4: C105.1 R147.2 ; port PD_OUT4
PD_OUT4_ZC: R201.1 ; port PD_OUT4_ZC
NetC101_1: C101.1 R138.2 R143.1 U17.2(IN_A-)
NetC101_2: C101.2 R138.1 R145.1 R200.2 TP44.1 U17.1(OUT_A)
NetC102_1: C102.1 R140.2 R146.1 U17.6(IN_B-)
NetC102_2: C102.2 R140.1 R147.1 R201.2 TP45.1 U17.7(OUT_B)
NetC107_2: C107.2 D17.1(K) L17.1 R148.1 R156.2 R157.2
NetC108_2: C108.2 D18.1(K) L18.1 R153.1 R158.2 R159.2
NetC136_1: C136.1 D31.1(A) D32.2(K) R215.1 R216.2 U22.2(VINP)
NetC136_2: C136.2 D33.2(K) D34.1(A) R218.1 R219.1 U22.3(VINN)
NetC141_1: C141.1 D35.1(A) D36.2(K) R221.1 R222.2 U23.2(VINP)
NetC141_2: C141.2 D37.2(K) D38.1(A) R224.1 R225.1 U23.3(VINN)
NetJ31_1: J31.1 R139.2
NetJ34_1: J34.1 R141.2
NetL15_2: L15.2 R217.1
NetL16_2: L16.2 R223.1
NetL17_2: L17.2 R216.1
NetL18_2: L18.2 R222.1
NetR139_1: R139.1 R142.2
NetR141_1: R141.1 R144.2
NetR142_1: R142.1 R148.2
NetR143_2: R143.2 U22.7(VOUTP)
NetR144_1: R144.1 R153.2
NetR146_2: R146.2 U23.7(VOUTP)
NetR149_1: R149.1 R151.2 R152.2 U17.3(IN_A+)
NetR149_2: R149.2 U22.6(VOUTN)
NetR150_1: R150.1 R154.2 R155.2 U17.5(IN_B+)
NetR150_2: R150.2 U23.6(VOUTN)
NetR217_2: R217.2 R218.2 R219.2
NetR223_2: R223.2 R224.2 R225.2

Not connected (* = marked no-connect by the designer): D31 3(C); D32 3(C); D33 3(C); D34 3(C); D35 3(C); D36 3(C); D37 3(C); D38 3(C); J31 2; J34 2; J49 2

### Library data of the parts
C101 C102 C104 C105 = 06033C101KAT2A: as C19 on sheet TIDA-00834_ISO-E2_Pg3_CT1_CT2
C103 C106 C132 C133 C137 C138 = 06033C104JAT2A: as C3 on sheet TIDA-00834_ISO-E2_Pg5_VOLTAGE
C107 C108 = C1608C0G1H102J: as C7 on sheet TIDA-00834_ISO-E2_Pg5_VOLTAGE
C134 C135 C139 C140 = GRM188R71C105KA12D: as C124 on sheet TIDA-00834_ISO-E2_Pg5_VOLTAGE
C136 C141 = 08055A331KAT2A: as C126 on sheet TIDA-00834_ISO-E2_Pg5_VOLTAGE
D17 D18 = PESD3V3L1BA: as D3 on sheet TIDA-00834_ISO-E2_Pg3_CT1_CT2
D31-D38 = BAV99WT1G: as D23 on sheet TIDA-00834_ISO-E2_Pg5_VOLTAGE
J31 J34 J49 = ED120/2DS: as J1 on sheet TIDA-00834_ISO-E2_Pg5_VOLTAGE
L15-L18 = FBMJ2125HM210NT: as L1 on sheet TIDA-00834_ISO-E2_Pg3_CT1_CT2
R138 R140 R151 R154 = RC0603FR-0768KL: as R1 on sheet TIDA-00834_ISO-E2_Pg5_VOLTAGE
R139 R141 R142 R144 R148 R153 = RC1206FR-07330KL: as R2 on sheet TIDA-00834_ISO-E2_Pg5_VOLTAGE
R143 R146 R149 R150 = RC0603FR-0716KL: as R6 on sheet TIDA-00834_ISO-E2_Pg5_VOLTAGE
R145 R147 = CRCW0603100RFKEA: as R45 on sheet TIDA-00834_ISO-E2_Pg3_CT1_CT2
R152 R155 = CRCW0603130KFKEA: as R15 on sheet TIDA-00834_ISO-E2_Pg5_VOLTAGE
R156-R159 R218 R219 R224 R225 = CRCW0603649RFKEA: as R19 on sheet TIDA-00834_ISO-E2_Pg5_VOLTAGE
R200 R201 = RC0603JR-070RL: as R42 on sheet TIDA-00834_ISO-E2_Pg3_CT1_CT2
R215 R221 = CRCW0603160KFKEA: as R199 on sheet TIDA-00834_ISO-E2_Pg5_VOLTAGE
R216 R217 R222 R223 = RC0603FR-0712RL: as R206 on sheet TIDA-00834_ISO-E2_Pg5_VOLTAGE
TP44 TP45 = TP-040_RND: as TP10 on sheet TIDA-00834_ISO-E2_Pg3_CT1_CT2
U17 = OPA2188AID: as U4 on sheet TIDA-00834_ISO-E2_Pg3_CT1_CT2
U22 U23 = AMC1301DWVR: as U20 on sheet TIDA-00834_ISO-E2_Pg5_VOLTAGE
